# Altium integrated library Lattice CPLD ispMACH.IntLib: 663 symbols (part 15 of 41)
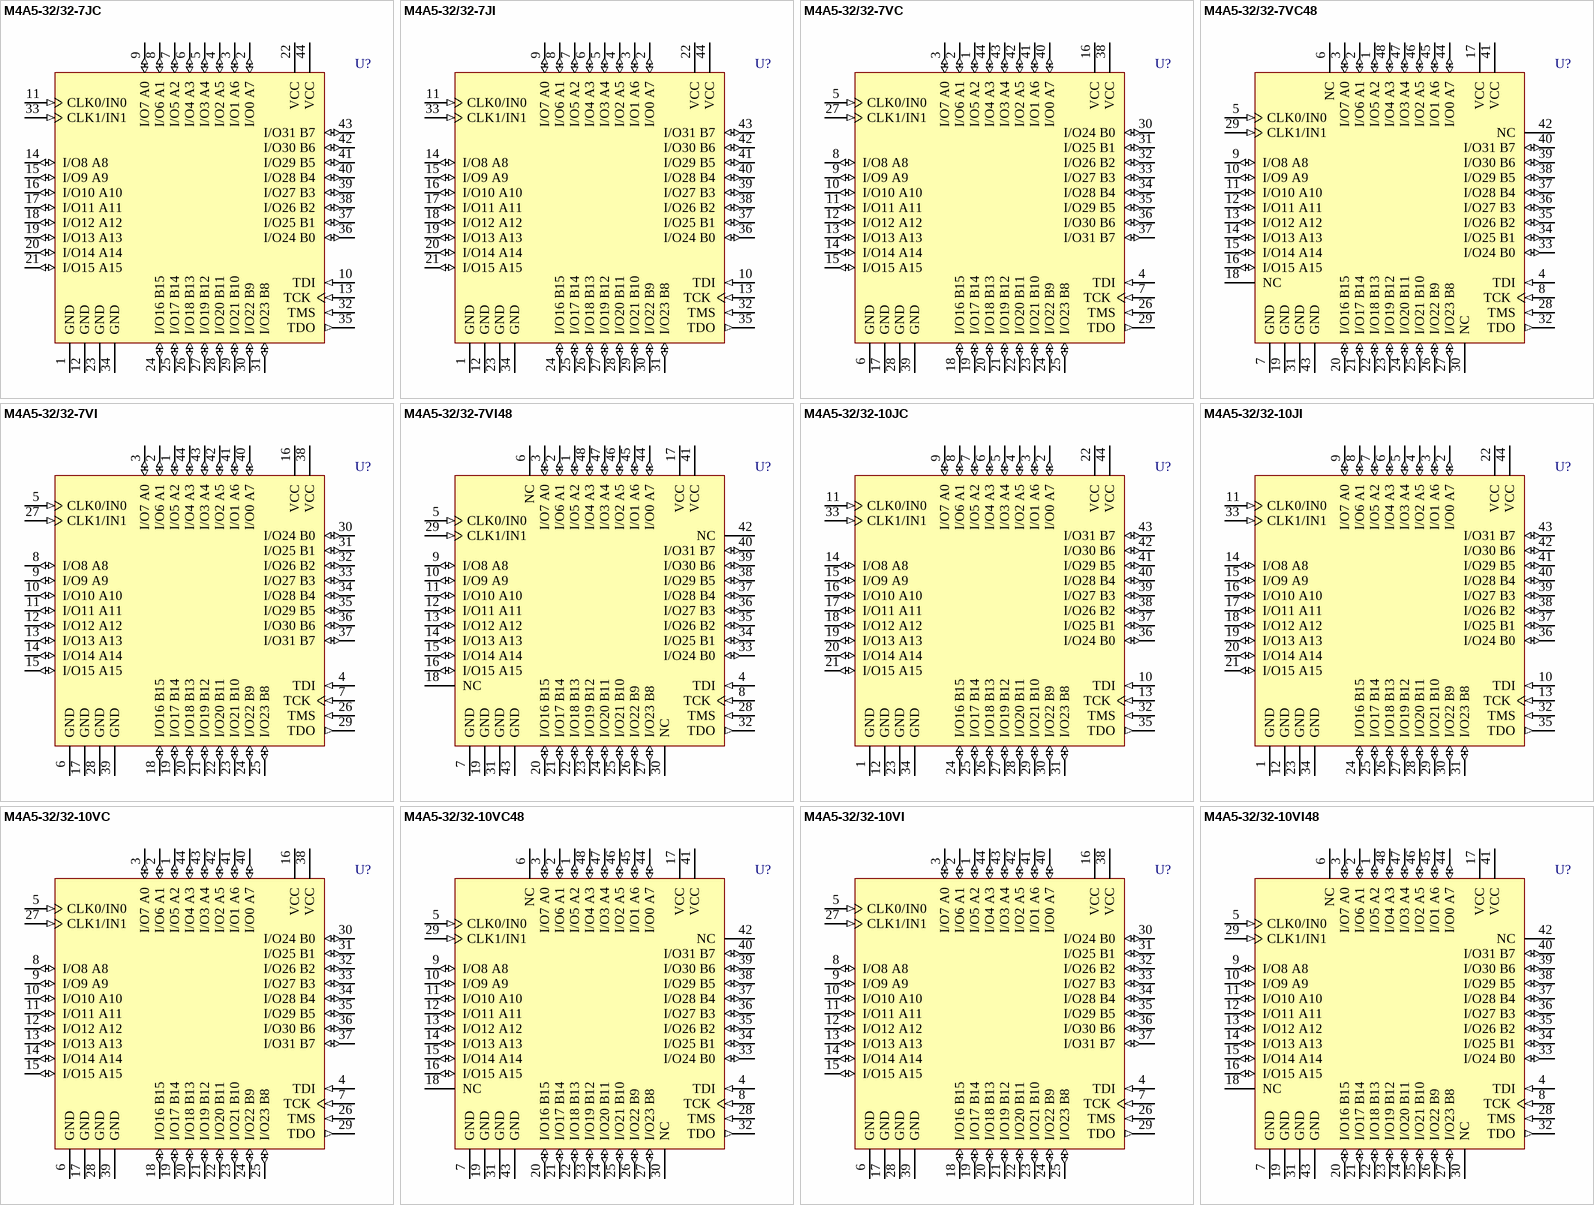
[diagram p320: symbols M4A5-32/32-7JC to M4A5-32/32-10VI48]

## M4A5-32/32-7JI
designator U?
High-Performance EE CMOS In-System Programmable Logic
footprint PLCC44_N (Leaded Chip Carrier, 44-Leads, Body 16.6x16.6mm, Pitch 1.27mm, IPC Medium Density)
footprint PLCC44_L (Leaded Chip Carrier, 44-Leads, Body 16.6x16.6mm, Pitch 1.27mm, IPC High Density)
footprint PLCC44_M (Leaded Chip Carrier, 44-Leads, Body 16.6x16.6mm, Pitch 1.27mm, IPC Low Density)
3D model M4A5-PLCC44 (44-Pin Leaded Chip Carrier 1.27 mm Pitch)
pins: 1 GND (power), 2 I/O0 A7 (io), 3 I/O1 A6 (io), 4 I/O2 A5 (io), 5 I/O3 A4 (io), 6 I/O4 A3 (io), 7 I/O5 A2 (io), 8 I/O6 A1 (io), 9 I/O7 A0 (io), 10 TDI (in), 11 CLK0/IN0 (in), 12 GND (power), 13 TCK (in), 14 I/O8 A8 (io), 15 I/O9 A9 (io), 16 I/O10 A10 (io), 17 I/O11 A11 (io), 18 I/O12 A12 (io), 19 I/O13 A13 (io), 20 I/O14 A14 (io), 21 I/O15 A15 (io), 22 VCC (power), 23 GND (power), 24 I/O16 B15 (io), 25 I/O17 B14 (io), 26 I/O18 B13 (io), 27 I/O19 B12 (io), 28 I/O20 B11 (io), 29 I/O21 B10 (io), 30 I/O22 B9 (io), 31 I/O23 B8 (io), 32 TMS (in), 33 CLK1/IN1 (in), 34 GND (power), 35 TDO (out), 36 I/O24 B0 (io), 37 I/O25 B1 (io), 38 I/O26 B2 (io), 39 I/O27 B3 (io), 40 I/O28 B4 (io), 41 I/O29 B5 (io), 42 I/O30 B6 (io), 43 I/O31 B7 (io), 44 VCC (power)

## M4A5-32/32-7VC
designator U?
High-Performance EE CMOS In-System Programmable Logic
footprint TQFP44_N (Thin QFP, 44-Leads, Body 10x10mm, Pitch 0.8mm, IPC Medium Density)
footprint TQFP44_L (Thin QFP, 44-Leads, Body 10x10mm, Pitch 0.8mm, IPC High Density)
footprint TQFP44_M (Thin QFP, 44-Leads, Body 10x10mm, Pitch 0.8mm, IPC Low Density)
3D model M4A5-TQFP44 (44-Pin Thin Quad Flat Pack 0.8 mm Pitch)
pins: 1 I/O5 A2 (io), 2 I/O6 A1 (io), 3 I/O7 A0 (io), 4 TDI (in), 5 CLK0/IN0 (in), 6 GND (power), 7 TCK (in), 8 I/O8 A8 (io), 9 I/O9 A9 (io), 10 I/O10 A10 (io), 11 I/O11 A11 (io), 12 I/O12 A12 (io), 13 I/O13 A13 (io), 14 I/O14 A14 (io), 15 I/O15 A15 (io), 16 VCC (power), 17 GND (power), 18 I/O16 B15 (io), 19 I/O17 B14 (io), 20 I/O18 B13 (io), 21 I/O19 B12 (io), 22 I/O20 B11 (io), 23 I/O21 B10 (io), 24 I/O22 B9 (io), 25 I/O23 B8 (io), 26 TMS (in), 27 CLK1/IN1 (in), 28 GND (power), 29 TDO (out), 30 I/O24 B0 (io), 31 I/O25 B1 (io), 32 I/O26 B2 (io), 33 I/O27 B3 (io), 34 I/O28 B4 (io), 35 I/O29 B5 (io), 36 I/O30 B6 (io), 37 I/O31 B7 (io), 38 VCC (power), 39 GND (power), 40 I/O0 A7 (io), 41 I/O1 A6 (io), 42 I/O2 A5 (io), 43 I/O3 A4 (io), 44 I/O4 A3 (io)

## M4A5-32/32-7VC48
designator U?
High-Performance EE CMOS In-System Programmable Logic
footprint TQFP48_N (Thin QFP, 48-Leads, Body 7x7mm, Pitch 0.5mm, IPC Medium Density)
footprint TQFP48_L (Thin QFP, 48-Leads, Body 7x7mm, Pitch 0.5mm, IPC High Density)
footprint TQFP48_M (Thin QFP, 48-Leads, Body 7x7mm, Pitch 0.5mm, IPC Low Density)
3D model M4A5-TQFP48 (48-Pin Thin Quad Flat Pack 0.5 mm Pitch)
pins: 1 I/O5 A2 (io), 2 I/O6 A1 (io), 3 I/O7 A0 (io), 4 TDI (in), 5 CLK0/IN0 (in), 6 NC, 7 GND (power), 8 TCK (in), 9 I/O8 A8 (io), 10 I/O9 A9 (io), 11 I/O10 A10 (io), 12 I/O11 A11 (io), 13 I/O12 A12 (io), 14 I/O13 A13 (io), 15 I/O14 A14 (io), 16 I/O15 A15 (io), 17 VCC (power), 18 NC, 19 GND (power), 20 I/O16 B15 (io), 21 I/O17 B14 (io), 22 I/O18 B13 (io), 23 I/O19 B12 (io), 24 I/O20 B11 (io), 25 I/O21 B10 (io), 26 I/O22 B9 (io), 27 I/O23 B8 (io), 28 TMS (in), 29 CLK1/IN1 (in), 30 NC, 31 GND (power), 32 TDO (out), 33 I/O24 B0 (io), 34 I/O25 B1 (io), 35 I/O26 B2 (io), 36 I/O27 B3 (io), 37 I/O28 B4 (io), 38 I/O29 B5 (io), 39 I/O30 B6 (io), 40 I/O31 B7 (io), 41 VCC (power), 42 NC, 43 GND (power), 44 I/O0 A7 (io), 45 I/O1 A6 (io), 46 I/O2 A5 (io), 47 I/O3 A4 (io), 48 I/O4 A3 (io)

## M4A5-32/32-7VI
designator U?
High-Performance EE CMOS In-System Programmable Logic
footprint TQFP44_N (Thin QFP, 44-Leads, Body 10x10mm, Pitch 0.8mm, IPC Medium Density)
footprint TQFP44_L (Thin QFP, 44-Leads, Body 10x10mm, Pitch 0.8mm, IPC High Density)
footprint TQFP44_M (Thin QFP, 44-Leads, Body 10x10mm, Pitch 0.8mm, IPC Low Density)
3D model M4A5-TQFP44 (44-Pin Thin Quad Flat Pack 0.8 mm Pitch)
pins: 1 I/O5 A2 (io), 2 I/O6 A1 (io), 3 I/O7 A0 (io), 4 TDI (in), 5 CLK0/IN0 (in), 6 GND (power), 7 TCK (in), 8 I/O8 A8 (io), 9 I/O9 A9 (io), 10 I/O10 A10 (io), 11 I/O11 A11 (io), 12 I/O12 A12 (io), 13 I/O13 A13 (io), 14 I/O14 A14 (io), 15 I/O15 A15 (io), 16 VCC (power), 17 GND (power), 18 I/O16 B15 (io), 19 I/O17 B14 (io), 20 I/O18 B13 (io), 21 I/O19 B12 (io), 22 I/O20 B11 (io), 23 I/O21 B10 (io), 24 I/O22 B9 (io), 25 I/O23 B8 (io), 26 TMS (in), 27 CLK1/IN1 (in), 28 GND (power), 29 TDO (out), 30 I/O24 B0 (io), 31 I/O25 B1 (io), 32 I/O26 B2 (io), 33 I/O27 B3 (io), 34 I/O28 B4 (io), 35 I/O29 B5 (io), 36 I/O30 B6 (io), 37 I/O31 B7 (io), 38 VCC (power), 39 GND (power), 40 I/O0 A7 (io), 41 I/O1 A6 (io), 42 I/O2 A5 (io), 43 I/O3 A4 (io), 44 I/O4 A3 (io)

## M4A5-32/32-7VI48
designator U?
High-Performance EE CMOS In-System Programmable Logic
footprint TQFP48_N (Thin QFP, 48-Leads, Body 7x7mm, Pitch 0.5mm, IPC Medium Density)
footprint TQFP48_L (Thin QFP, 48-Leads, Body 7x7mm, Pitch 0.5mm, IPC High Density)
footprint TQFP48_M (Thin QFP, 48-Leads, Body 7x7mm, Pitch 0.5mm, IPC Low Density)
3D model M4A5-TQFP48 (48-Pin Thin Quad Flat Pack 0.5 mm Pitch)
pins: 1 I/O5 A2 (io), 2 I/O6 A1 (io), 3 I/O7 A0 (io), 4 TDI (in), 5 CLK0/IN0 (in), 6 NC, 7 GND (power), 8 TCK (in), 9 I/O8 A8 (io), 10 I/O9 A9 (io), 11 I/O10 A10 (io), 12 I/O11 A11 (io), 13 I/O12 A12 (io), 14 I/O13 A13 (io), 15 I/O14 A14 (io), 16 I/O15 A15 (io), 17 VCC (power), 18 NC, 19 GND (power), 20 I/O16 B15 (io), 21 I/O17 B14 (io), 22 I/O18 B13 (io), 23 I/O19 B12 (io), 24 I/O20 B11 (io), 25 I/O21 B10 (io), 26 I/O22 B9 (io), 27 I/O23 B8 (io), 28 TMS (in), 29 CLK1/IN1 (in), 30 NC, 31 GND (power), 32 TDO (out), 33 I/O24 B0 (io), 34 I/O25 B1 (io), 35 I/O26 B2 (io), 36 I/O27 B3 (io), 37 I/O28 B4 (io), 38 I/O29 B5 (io), 39 I/O30 B6 (io), 40 I/O31 B7 (io), 41 VCC (power), 42 NC, 43 GND (power), 44 I/O0 A7 (io), 45 I/O1 A6 (io), 46 I/O2 A5 (io), 47 I/O3 A4 (io), 48 I/O4 A3 (io)

## M4A5-32/32-10JC
designator U?
High-Performance EE CMOS In-System Programmable Logic
footprint PLCC44_N (Leaded Chip Carrier, 44-Leads, Body 16.6x16.6mm, Pitch 1.27mm, IPC Medium Density)
footprint PLCC44_L (Leaded Chip Carrier, 44-Leads, Body 16.6x16.6mm, Pitch 1.27mm, IPC High Density)
footprint PLCC44_M (Leaded Chip Carrier, 44-Leads, Body 16.6x16.6mm, Pitch 1.27mm, IPC Low Density)
3D model M4A5-PLCC44 (44-Pin Leaded Chip Carrier 1.27 mm Pitch)
pins: 1 GND (power), 2 I/O0 A7 (io), 3 I/O1 A6 (io), 4 I/O2 A5 (io), 5 I/O3 A4 (io), 6 I/O4 A3 (io), 7 I/O5 A2 (io), 8 I/O6 A1 (io), 9 I/O7 A0 (io), 10 TDI (in), 11 CLK0/IN0 (in), 12 GND (power), 13 TCK (in), 14 I/O8 A8 (io), 15 I/O9 A9 (io), 16 I/O10 A10 (io), 17 I/O11 A11 (io), 18 I/O12 A12 (io), 19 I/O13 A13 (io), 20 I/O14 A14 (io), 21 I/O15 A15 (io), 22 VCC (power), 23 GND (power), 24 I/O16 B15 (io), 25 I/O17 B14 (io), 26 I/O18 B13 (io), 27 I/O19 B12 (io), 28 I/O20 B11 (io), 29 I/O21 B10 (io), 30 I/O22 B9 (io), 31 I/O23 B8 (io), 32 TMS (in), 33 CLK1/IN1 (in), 34 GND (power), 35 TDO (out), 36 I/O24 B0 (io), 37 I/O25 B1 (io), 38 I/O26 B2 (io), 39 I/O27 B3 (io), 40 I/O28 B4 (io), 41 I/O29 B5 (io), 42 I/O30 B6 (io), 43 I/O31 B7 (io), 44 VCC (power)

## M4A5-32/32-10JI
designator U?
High-Performance EE CMOS In-System Programmable Logic
footprint PLCC44_N (Leaded Chip Carrier, 44-Leads, Body 16.6x16.6mm, Pitch 1.27mm, IPC Medium Density)
footprint PLCC44_L (Leaded Chip Carrier, 44-Leads, Body 16.6x16.6mm, Pitch 1.27mm, IPC High Density)
footprint PLCC44_M (Leaded Chip Carrier, 44-Leads, Body 16.6x16.6mm, Pitch 1.27mm, IPC Low Density)
3D model M4A5-PLCC44 (44-Pin Leaded Chip Carrier 1.27 mm Pitch)
pins: 1 GND (power), 2 I/O0 A7 (io), 3 I/O1 A6 (io), 4 I/O2 A5 (io), 5 I/O3 A4 (io), 6 I/O4 A3 (io), 7 I/O5 A2 (io), 8 I/O6 A1 (io), 9 I/O7 A0 (io), 10 TDI (in), 11 CLK0/IN0 (in), 12 GND (power), 13 TCK (in), 14 I/O8 A8 (io), 15 I/O9 A9 (io), 16 I/O10 A10 (io), 17 I/O11 A11 (io), 18 I/O12 A12 (io), 19 I/O13 A13 (io), 20 I/O14 A14 (io), 21 I/O15 A15 (io), 22 VCC (power), 23 GND (power), 24 I/O16 B15 (io), 25 I/O17 B14 (io), 26 I/O18 B13 (io), 27 I/O19 B12 (io), 28 I/O20 B11 (io), 29 I/O21 B10 (io), 30 I/O22 B9 (io), 31 I/O23 B8 (io), 32 TMS (in), 33 CLK1/IN1 (in), 34 GND (power), 35 TDO (out), 36 I/O24 B0 (io), 37 I/O25 B1 (io), 38 I/O26 B2 (io), 39 I/O27 B3 (io), 40 I/O28 B4 (io), 41 I/O29 B5 (io), 42 I/O30 B6 (io), 43 I/O31 B7 (io), 44 VCC (power)

## M4A5-32/32-10VC
designator U?
High-Performance EE CMOS In-System Programmable Logic
footprint TQFP44_N (Thin QFP, 44-Leads, Body 10x10mm, Pitch 0.8mm, IPC Medium Density)
footprint TQFP44_L (Thin QFP, 44-Leads, Body 10x10mm, Pitch 0.8mm, IPC High Density)
footprint TQFP44_M (Thin QFP, 44-Leads, Body 10x10mm, Pitch 0.8mm, IPC Low Density)
3D model M4A5-TQFP44 (44-Pin Thin Quad Flat Pack 0.8 mm Pitch)
pins: 1 I/O5 A2 (io), 2 I/O6 A1 (io), 3 I/O7 A0 (io), 4 TDI (in), 5 CLK0/IN0 (in), 6 GND (power), 7 TCK (in), 8 I/O8 A8 (io), 9 I/O9 A9 (io), 10 I/O10 A10 (io), 11 I/O11 A11 (io), 12 I/O12 A12 (io), 13 I/O13 A13 (io), 14 I/O14 A14 (io), 15 I/O15 A15 (io), 16 VCC (power), 17 GND (power), 18 I/O16 B15 (io), 19 I/O17 B14 (io), 20 I/O18 B13 (io), 21 I/O19 B12 (io), 22 I/O20 B11 (io), 23 I/O21 B10 (io), 24 I/O22 B9 (io), 25 I/O23 B8 (io), 26 TMS (in), 27 CLK1/IN1 (in), 28 GND (power), 29 TDO (out), 30 I/O24 B0 (io), 31 I/O25 B1 (io), 32 I/O26 B2 (io), 33 I/O27 B3 (io), 34 I/O28 B4 (io), 35 I/O29 B5 (io), 36 I/O30 B6 (io), 37 I/O31 B7 (io), 38 VCC (power), 39 GND (power), 40 I/O0 A7 (io), 41 I/O1 A6 (io), 42 I/O2 A5 (io), 43 I/O3 A4 (io), 44 I/O4 A3 (io)

## M4A5-32/32-10VC48
designator U?
High-Performance EE CMOS In-System Programmable Logic
footprint TQFP48_N (Thin QFP, 48-Leads, Body 7x7mm, Pitch 0.5mm, IPC Medium Density)
footprint TQFP48_L (Thin QFP, 48-Leads, Body 7x7mm, Pitch 0.5mm, IPC High Density)
footprint TQFP48_M (Thin QFP, 48-Leads, Body 7x7mm, Pitch 0.5mm, IPC Low Density)
3D model M4A5-TQFP48 (48-Pin Thin Quad Flat Pack 0.5 mm Pitch)
pins: 1 I/O5 A2 (io), 2 I/O6 A1 (io), 3 I/O7 A0 (io), 4 TDI (in), 5 CLK0/IN0 (in), 6 NC, 7 GND (power), 8 TCK (in), 9 I/O8 A8 (io), 10 I/O9 A9 (io), 11 I/O10 A10 (io), 12 I/O11 A11 (io), 13 I/O12 A12 (io), 14 I/O13 A13 (io), 15 I/O14 A14 (io), 16 I/O15 A15 (io), 17 VCC (power), 18 NC, 19 GND (power), 20 I/O16 B15 (io), 21 I/O17 B14 (io), 22 I/O18 B13 (io), 23 I/O19 B12 (io), 24 I/O20 B11 (io), 25 I/O21 B10 (io), 26 I/O22 B9 (io), 27 I/O23 B8 (io), 28 TMS (in), 29 CLK1/IN1 (in), 30 NC, 31 GND (power), 32 TDO (out), 33 I/O24 B0 (io), 34 I/O25 B1 (io), 35 I/O26 B2 (io), 36 I/O27 B3 (io), 37 I/O28 B4 (io), 38 I/O29 B5 (io), 39 I/O30 B6 (io), 40 I/O31 B7 (io), 41 VCC (power), 42 NC, 43 GND (power), 44 I/O0 A7 (io), 45 I/O1 A6 (io), 46 I/O2 A5 (io), 47 I/O3 A4 (io), 48 I/O4 A3 (io)

## M4A5-32/32-10VI
designator U?
High-Performance EE CMOS In-System Programmable Logic
footprint TQFP44_N (Thin QFP, 44-Leads, Body 10x10mm, Pitch 0.8mm, IPC Medium Density)
footprint TQFP44_L (Thin QFP, 44-Leads, Body 10x10mm, Pitch 0.8mm, IPC High Density)
footprint TQFP44_M (Thin QFP, 44-Leads, Body 10x10mm, Pitch 0.8mm, IPC Low Density)
3D model M4A5-TQFP44 (44-Pin Thin Quad Flat Pack 0.8 mm Pitch)
pins: 1 I/O5 A2 (io), 2 I/O6 A1 (io), 3 I/O7 A0 (io), 4 TDI (in), 5 CLK0/IN0 (in), 6 GND (power), 7 TCK (in), 8 I/O8 A8 (io), 9 I/O9 A9 (io), 10 I/O10 A10 (io), 11 I/O11 A11 (io), 12 I/O12 A12 (io), 13 I/O13 A13 (io), 14 I/O14 A14 (io), 15 I/O15 A15 (io), 16 VCC (power), 17 GND (power), 18 I/O16 B15 (io), 19 I/O17 B14 (io), 20 I/O18 B13 (io), 21 I/O19 B12 (io), 22 I/O20 B11 (io), 23 I/O21 B10 (io), 24 I/O22 B9 (io), 25 I/O23 B8 (io), 26 TMS (in), 27 CLK1/IN1 (in), 28 GND (power), 29 TDO (out), 30 I/O24 B0 (io), 31 I/O25 B1 (io), 32 I/O26 B2 (io), 33 I/O27 B3 (io), 34 I/O28 B4 (io), 35 I/O29 B5 (io), 36 I/O30 B6 (io), 37 I/O31 B7 (io), 38 VCC (power), 39 GND (power), 40 I/O0 A7 (io), 41 I/O1 A6 (io), 42 I/O2 A5 (io), 43 I/O3 A4 (io), 44 I/O4 A3 (io)

## M4A5-32/32-10VI48
designator U?
High-Performance EE CMOS In-System Programmable Logic
footprint TQFP48_N (Thin QFP, 48-Leads, Body 7x7mm, Pitch 0.5mm, IPC Medium Density)
footprint TQFP48_L (Thin QFP, 48-Leads, Body 7x7mm, Pitch 0.5mm, IPC High Density)
footprint TQFP48_M (Thin QFP, 48-Leads, Body 7x7mm, Pitch 0.5mm, IPC Low Density)
3D model M4A5-TQFP48 (48-Pin Thin Quad Flat Pack 0.5 mm Pitch)
pins: 1 I/O5 A2 (io), 2 I/O6 A1 (io), 3 I/O7 A0 (io), 4 TDI (in), 5 CLK0/IN0 (in), 6 NC, 7 GND (power), 8 TCK (in), 9 I/O8 A8 (io), 10 I/O9 A9 (io), 11 I/O10 A10 (io), 12 I/O11 A11 (io), 13 I/O12 A12 (io), 14 I/O13 A13 (io), 15 I/O14 A14 (io), 16 I/O15 A15 (io), 17 VCC (power), 18 NC, 19 GND (power), 20 I/O16 B15 (io), 21 I/O17 B14 (io), 22 I/O18 B13 (io), 23 I/O19 B12 (io), 24 I/O20 B11 (io), 25 I/O21 B10 (io), 26 I/O22 B9 (io), 27 I/O23 B8 (io), 28 TMS (in), 29 CLK1/IN1 (in), 30 NC, 31 GND (power), 32 TDO (out), 33 I/O24 B0 (io), 34 I/O25 B1 (io), 35 I/O26 B2 (io), 36 I/O27 B3 (io), 37 I/O28 B4 (io), 38 I/O29 B5 (io), 39 I/O30 B6 (io), 40 I/O31 B7 (io), 41 VCC (power), 42 NC, 43 GND (power), 44 I/O0 A7 (io), 45 I/O1 A6 (io), 46 I/O2 A5 (io), 47 I/O3 A4 (io), 48 I/O4 A3 (io)

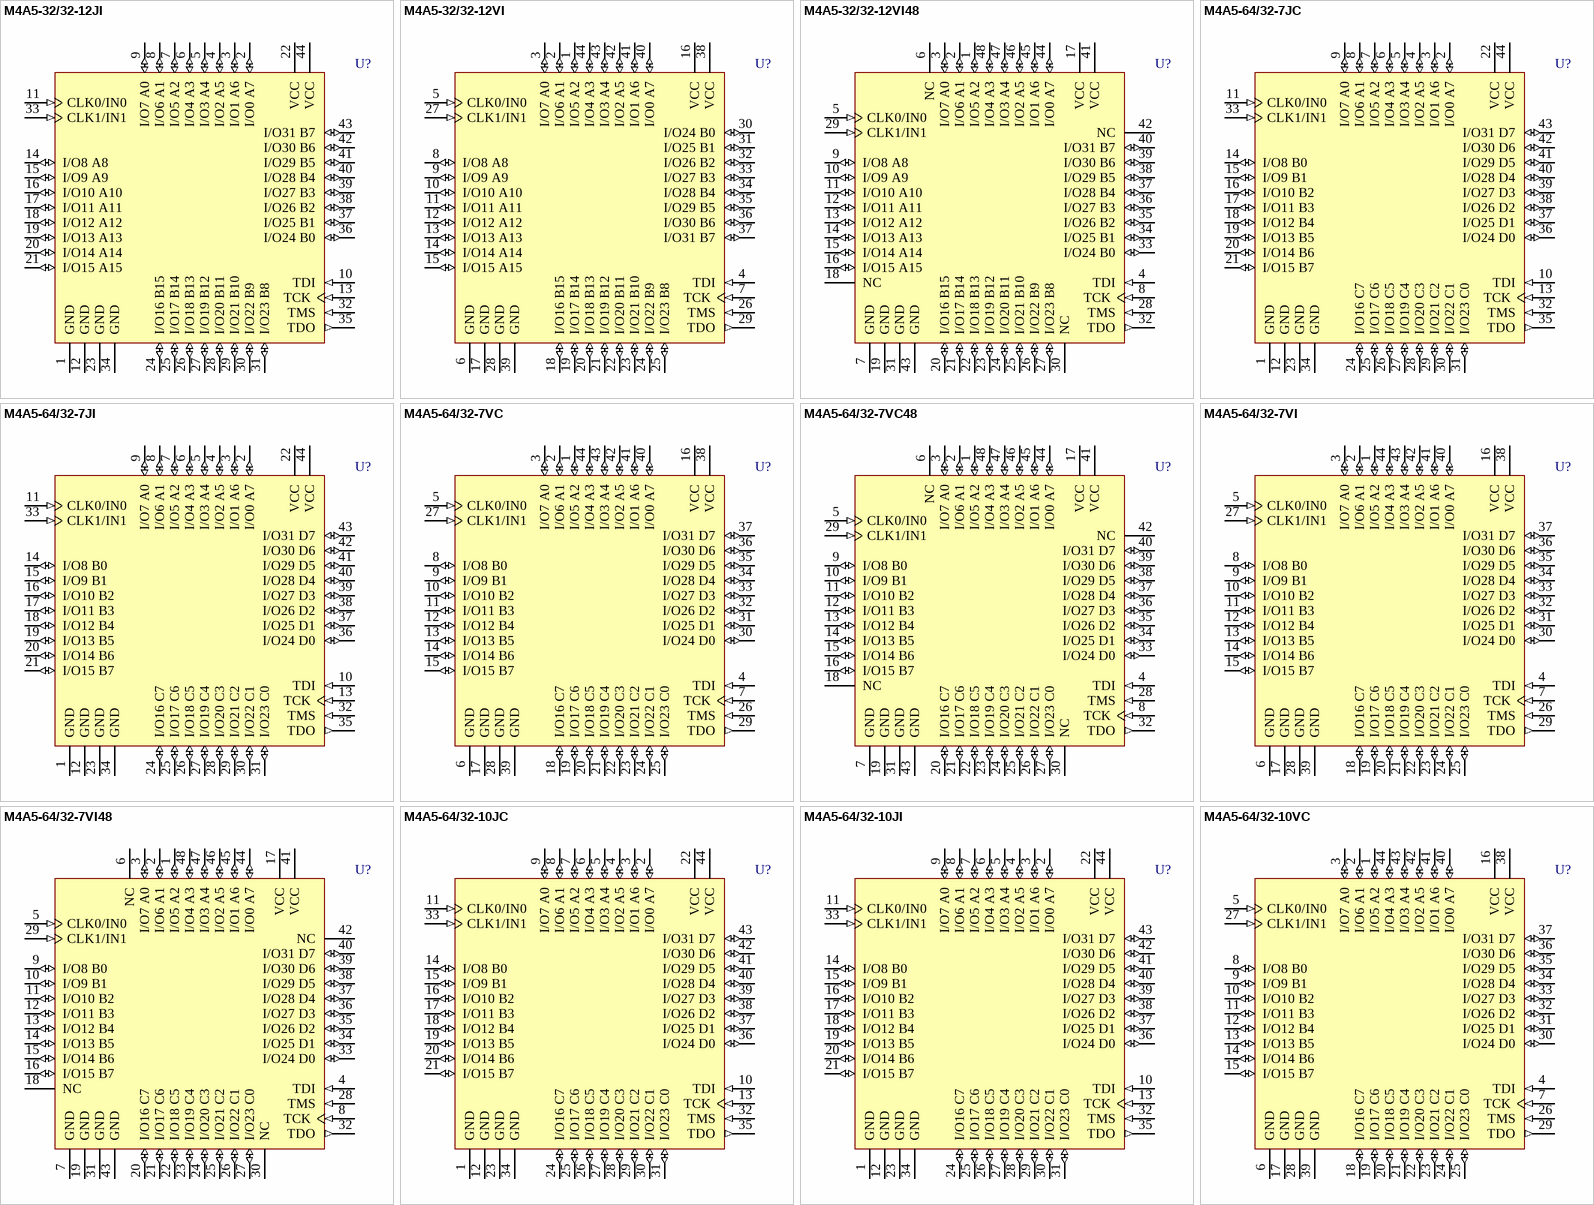
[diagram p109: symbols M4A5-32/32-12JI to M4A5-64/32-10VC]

## M4A5-32/32-12JI
designator U?
High-Performance EE CMOS In-System Programmable Logic
footprint PLCC44_N (Leaded Chip Carrier, 44-Leads, Body 16.6x16.6mm, Pitch 1.27mm, IPC Medium Density)
footprint PLCC44_L (Leaded Chip Carrier, 44-Leads, Body 16.6x16.6mm, Pitch 1.27mm, IPC High Density)
footprint PLCC44_M (Leaded Chip Carrier, 44-Leads, Body 16.6x16.6mm, Pitch 1.27mm, IPC Low Density)
3D model M4A5-PLCC44 (44-Pin Leaded Chip Carrier 1.27 mm Pitch)
pins: 1 GND (power), 2 I/O0 A7 (io), 3 I/O1 A6 (io), 4 I/O2 A5 (io), 5 I/O3 A4 (io), 6 I/O4 A3 (io), 7 I/O5 A2 (io), 8 I/O6 A1 (io), 9 I/O7 A0 (io), 10 TDI (in), 11 CLK0/IN0 (in), 12 GND (power), 13 TCK (in), 14 I/O8 A8 (io), 15 I/O9 A9 (io), 16 I/O10 A10 (io), 17 I/O11 A11 (io), 18 I/O12 A12 (io), 19 I/O13 A13 (io), 20 I/O14 A14 (io), 21 I/O15 A15 (io), 22 VCC (power), 23 GND (power), 24 I/O16 B15 (io), 25 I/O17 B14 (io), 26 I/O18 B13 (io), 27 I/O19 B12 (io), 28 I/O20 B11 (io), 29 I/O21 B10 (io), 30 I/O22 B9 (io), 31 I/O23 B8 (io), 32 TMS (in), 33 CLK1/IN1 (in), 34 GND (power), 35 TDO (out), 36 I/O24 B0 (io), 37 I/O25 B1 (io), 38 I/O26 B2 (io), 39 I/O27 B3 (io), 40 I/O28 B4 (io), 41 I/O29 B5 (io), 42 I/O30 B6 (io), 43 I/O31 B7 (io), 44 VCC (power)

## M4A5-32/32-12VI
designator U?
High-Performance EE CMOS In-System Programmable Logic
footprint TQFP44_N (Thin QFP, 44-Leads, Body 10x10mm, Pitch 0.8mm, IPC Medium Density)
footprint TQFP44_L (Thin QFP, 44-Leads, Body 10x10mm, Pitch 0.8mm, IPC High Density)
footprint TQFP44_M (Thin QFP, 44-Leads, Body 10x10mm, Pitch 0.8mm, IPC Low Density)
3D model M4A5-TQFP44 (44-Pin Thin Quad Flat Pack 0.8 mm Pitch)
pins: 1 I/O5 A2 (io), 2 I/O6 A1 (io), 3 I/O7 A0 (io), 4 TDI (in), 5 CLK0/IN0 (in), 6 GND (power), 7 TCK (in), 8 I/O8 A8 (io), 9 I/O9 A9 (io), 10 I/O10 A10 (io), 11 I/O11 A11 (io), 12 I/O12 A12 (io), 13 I/O13 A13 (io), 14 I/O14 A14 (io), 15 I/O15 A15 (io), 16 VCC (power), 17 GND (power), 18 I/O16 B15 (io), 19 I/O17 B14 (io), 20 I/O18 B13 (io), 21 I/O19 B12 (io), 22 I/O20 B11 (io), 23 I/O21 B10 (io), 24 I/O22 B9 (io), 25 I/O23 B8 (io), 26 TMS (in), 27 CLK1/IN1 (in), 28 GND (power), 29 TDO (out), 30 I/O24 B0 (io), 31 I/O25 B1 (io), 32 I/O26 B2 (io), 33 I/O27 B3 (io), 34 I/O28 B4 (io), 35 I/O29 B5 (io), 36 I/O30 B6 (io), 37 I/O31 B7 (io), 38 VCC (power), 39 GND (power), 40 I/O0 A7 (io), 41 I/O1 A6 (io), 42 I/O2 A5 (io), 43 I/O3 A4 (io), 44 I/O4 A3 (io)

## M4A5-32/32-12VI48
designator U?
High-Performance EE CMOS In-System Programmable Logic
footprint TQFP48_N (Thin QFP, 48-Leads, Body 7x7mm, Pitch 0.5mm, IPC Medium Density)
footprint TQFP48_L (Thin QFP, 48-Leads, Body 7x7mm, Pitch 0.5mm, IPC High Density)
footprint TQFP48_M (Thin QFP, 48-Leads, Body 7x7mm, Pitch 0.5mm, IPC Low Density)
3D model M4A5-TQFP48 (48-Pin Thin Quad Flat Pack 0.5 mm Pitch)
pins: 1 I/O5 A2 (io), 2 I/O6 A1 (io), 3 I/O7 A0 (io), 4 TDI (in), 5 CLK0/IN0 (in), 6 NC, 7 GND (power), 8 TCK (in), 9 I/O8 A8 (io), 10 I/O9 A9 (io), 11 I/O10 A10 (io), 12 I/O11 A11 (io), 13 I/O12 A12 (io), 14 I/O13 A13 (io), 15 I/O14 A14 (io), 16 I/O15 A15 (io), 17 VCC (power), 18 NC, 19 GND (power), 20 I/O16 B15 (io), 21 I/O17 B14 (io), 22 I/O18 B13 (io), 23 I/O19 B12 (io), 24 I/O20 B11 (io), 25 I/O21 B10 (io), 26 I/O22 B9 (io), 27 I/O23 B8 (io), 28 TMS (in), 29 CLK1/IN1 (in), 30 NC, 31 GND (power), 32 TDO (out), 33 I/O24 B0 (io), 34 I/O25 B1 (io), 35 I/O26 B2 (io), 36 I/O27 B3 (io), 37 I/O28 B4 (io), 38 I/O29 B5 (io), 39 I/O30 B6 (io), 40 I/O31 B7 (io), 41 VCC (power), 42 NC, 43 GND (power), 44 I/O0 A7 (io), 45 I/O1 A6 (io), 46 I/O2 A5 (io), 47 I/O3 A4 (io), 48 I/O4 A3 (io)

## M4A5-64/32-7JC
designator U?
High-Performance EE CMOS In-System Programmable Logic
footprint PLCC44_N (Leaded Chip Carrier, 44-Leads, Body 16.6x16.6mm, Pitch 1.27mm, IPC Medium Density)
footprint PLCC44_L (Leaded Chip Carrier, 44-Leads, Body 16.6x16.6mm, Pitch 1.27mm, IPC High Density)
footprint PLCC44_M (Leaded Chip Carrier, 44-Leads, Body 16.6x16.6mm, Pitch 1.27mm, IPC Low Density)
3D model M4A5-PLCC44 (44-Pin Leaded Chip Carrier 1.27 mm Pitch)
pins: 1 GND (power), 2 I/O0 A7 (io), 3 I/O1 A6 (io), 4 I/O2 A5 (io), 5 I/O3 A4 (io), 6 I/O4 A3 (io), 7 I/O5 A2 (io), 8 I/O6 A1 (io), 9 I/O7 A0 (io), 10 TDI (in), 11 CLK0/IN0 (in), 12 GND (power), 13 TCK (in), 14 I/O8 B0 (io), 15 I/O9 B1 (io), 16 I/O10 B2 (io), 17 I/O11 B3 (io), 18 I/O12 B4 (io), 19 I/O13 B5 (io), 20 I/O14 B6 (io), 21 I/O15 B7 (io), 22 VCC (power), 23 GND (power), 24 I/O16 C7 (io), 25 I/O17 C6 (io), 26 I/O18 C5 (io), 27 I/O19 C4 (io), 28 I/O20 C3 (io), 29 I/O21 C2 (io), 30 I/O22 C1 (io), 31 I/O23 C0 (io), 32 TMS (in), 33 CLK1/IN1 (in), 34 GND (power), 35 TDO (out), 36 I/O24 D0 (io), 37 I/O25 D1 (io), 38 I/O26 D2 (io), 39 I/O27 D3 (io), 40 I/O28 D4 (io), 41 I/O29 D5 (io), 42 I/O30 D6 (io), 43 I/O31 D7 (io), 44 VCC (power)

## M4A5-64/32-7JI
designator U?
High-Performance EE CMOS In-System Programmable Logic
footprint PLCC44_N (Leaded Chip Carrier, 44-Leads, Body 16.6x16.6mm, Pitch 1.27mm, IPC Medium Density)
footprint PLCC44_L (Leaded Chip Carrier, 44-Leads, Body 16.6x16.6mm, Pitch 1.27mm, IPC High Density)
footprint PLCC44_M (Leaded Chip Carrier, 44-Leads, Body 16.6x16.6mm, Pitch 1.27mm, IPC Low Density)
3D model M4A5-PLCC44 (44-Pin Leaded Chip Carrier 1.27 mm Pitch)
pins: 1 GND (power), 2 I/O0 A7 (io), 3 I/O1 A6 (io), 4 I/O2 A5 (io), 5 I/O3 A4 (io), 6 I/O4 A3 (io), 7 I/O5 A2 (io), 8 I/O6 A1 (io), 9 I/O7 A0 (io), 10 TDI (in), 11 CLK0/IN0 (in), 12 GND (power), 13 TCK (in), 14 I/O8 B0 (io), 15 I/O9 B1 (io), 16 I/O10 B2 (io), 17 I/O11 B3 (io), 18 I/O12 B4 (io), 19 I/O13 B5 (io), 20 I/O14 B6 (io), 21 I/O15 B7 (io), 22 VCC (power), 23 GND (power), 24 I/O16 C7 (io), 25 I/O17 C6 (io), 26 I/O18 C5 (io), 27 I/O19 C4 (io), 28 I/O20 C3 (io), 29 I/O21 C2 (io), 30 I/O22 C1 (io), 31 I/O23 C0 (io), 32 TMS (in), 33 CLK1/IN1 (in), 34 GND (power), 35 TDO (out), 36 I/O24 D0 (io), 37 I/O25 D1 (io), 38 I/O26 D2 (io), 39 I/O27 D3 (io), 40 I/O28 D4 (io), 41 I/O29 D5 (io), 42 I/O30 D6 (io), 43 I/O31 D7 (io), 44 VCC (power)

## M4A5-64/32-7VC
designator U?
High-Performance EE CMOS In-System Programmable Logic
footprint TQFP44_N (Thin QFP, 44-Leads, Body 10x10mm, Pitch 0.8mm, IPC Medium Density)
footprint TQFP44_L (Thin QFP, 44-Leads, Body 10x10mm, Pitch 0.8mm, IPC High Density)
footprint TQFP44_M (Thin QFP, 44-Leads, Body 10x10mm, Pitch 0.8mm, IPC Low Density)
3D model M4A5-TQFP44 (44-Pin Thin Quad Flat Pack 0.8 mm Pitch)
pins: 1 I/O5 A2 (io), 2 I/O6 A1 (io), 3 I/O7 A0 (io), 4 TDI (in), 5 CLK0/IN0 (in), 6 GND (power), 7 TCK (in), 8 I/O8 B0 (io), 9 I/O9 B1 (io), 10 I/O10 B2 (io), 11 I/O11 B3 (io), 12 I/O12 B4 (io), 13 I/O13 B5 (io), 14 I/O14 B6 (io), 15 I/O15 B7 (io), 16 VCC (power), 17 GND (power), 18 I/O16 C7 (io), 19 I/O17 C6 (io), 20 I/O18 C5 (io), 21 I/O19 C4 (io), 22 I/O20 C3 (io), 23 I/O21 C2 (io), 24 I/O22 C1 (io), 25 I/O23 C0 (io), 26 TMS (in), 27 CLK1/IN1 (in), 28 GND (power), 29 TDO (out), 30 I/O24 D0 (io), 31 I/O25 D1 (io), 32 I/O26 D2 (io), 33 I/O27 D3 (io), 34 I/O28 D4 (io), 35 I/O29 D5 (io), 36 I/O30 D6 (io), 37 I/O31 D7 (io), 38 VCC (power), 39 GND (power), 40 I/O0 A7 (io), 41 I/O1 A6 (io), 42 I/O2 A5 (io), 43 I/O3 A4 (io), 44 I/O4 A3 (io)

## M4A5-64/32-7VC48
designator U?
High-Performance EE CMOS In-System Programmable Logic
footprint TQFP48_N (Thin QFP, 48-Leads, Body 7x7mm, Pitch 0.5mm, IPC Medium Density)
footprint TQFP48_L (Thin QFP, 48-Leads, Body 7x7mm, Pitch 0.5mm, IPC High Density)
footprint TQFP48_M (Thin QFP, 48-Leads, Body 7x7mm, Pitch 0.5mm, IPC Low Density)
3D model M4A5-TQFP48 (48-Pin Thin Quad Flat Pack 0.5 mm Pitch)
pins: 1 I/O5 A2 (io), 2 I/O6 A1 (io), 3 I/O7 A0 (io), 4 TDI (in), 5 CLK0/IN0 (in), 6 NC, 7 GND (power), 8 TCK (in), 9 I/O8 B0 (io), 10 I/O9 B1 (io), 11 I/O10 B2 (io), 12 I/O11 B3 (io), 13 I/O12 B4 (io), 14 I/O13 B5 (io), 15 I/O14 B6 (io), 16 I/O15 B7 (io), 17 VCC (power), 18 NC, 19 GND (power), 20 I/O16 C7 (io), 21 I/O17 C6 (io), 22 I/O18 C5 (io), 23 I/O19 C4 (io), 24 I/O20 C3 (io), 25 I/O21 C2 (io), 26 I/O22 C1 (io), 27 I/O23 C0 (io), 28 TMS (in), 29 CLK1/IN1 (in), 30 NC, 31 GND (power), 32 TDO (out), 33 I/O24 D0 (io), 34 I/O25 D1 (io), 35 I/O26 D2 (io), 36 I/O27 D3 (io), 37 I/O28 D4 (io), 38 I/O29 D5 (io), 39 I/O30 D6 (io), 40 I/O31 D7 (io), 41 VCC (power), 42 NC, 43 GND (power), 44 I/O0 A7 (io), 45 I/O1 A6 (io), 46 I/O2 A5 (io), 47 I/O3 A4 (io), 48 I/O4 A3 (io)

## M4A5-64/32-7VI
designator U?
High-Performance EE CMOS In-System Programmable Logic
footprint TQFP44_N (Thin QFP, 44-Leads, Body 10x10mm, Pitch 0.8mm, IPC Medium Density)
footprint TQFP44_L (Thin QFP, 44-Leads, Body 10x10mm, Pitch 0.8mm, IPC High Density)
footprint TQFP44_M (Thin QFP, 44-Leads, Body 10x10mm, Pitch 0.8mm, IPC Low Density)
3D model M4A5-TQFP44 (44-Pin Thin Quad Flat Pack 0.8 mm Pitch)
pins: 1 I/O5 A2 (io), 2 I/O6 A1 (io), 3 I/O7 A0 (io), 4 TDI (in), 5 CLK0/IN0 (in), 6 GND (power), 7 TCK (in), 8 I/O8 B0 (io), 9 I/O9 B1 (io), 10 I/O10 B2 (io), 11 I/O11 B3 (io), 12 I/O12 B4 (io), 13 I/O13 B5 (io), 14 I/O14 B6 (io), 15 I/O15 B7 (io), 16 VCC (power), 17 GND (power), 18 I/O16 C7 (io), 19 I/O17 C6 (io), 20 I/O18 C5 (io), 21 I/O19 C4 (io), 22 I/O20 C3 (io), 23 I/O21 C2 (io), 24 I/O22 C1 (io), 25 I/O23 C0 (io), 26 TMS (in), 27 CLK1/IN1 (in), 28 GND (power), 29 TDO (out), 30 I/O24 D0 (io), 31 I/O25 D1 (io), 32 I/O26 D2 (io), 33 I/O27 D3 (io), 34 I/O28 D4 (io), 35 I/O29 D5 (io), 36 I/O30 D6 (io), 37 I/O31 D7 (io), 38 VCC (power), 39 GND (power), 40 I/O0 A7 (io), 41 I/O1 A6 (io), 42 I/O2 A5 (io), 43 I/O3 A4 (io), 44 I/O4 A3 (io)

## M4A5-64/32-7VI48
designator U?
High-Performance EE CMOS In-System Programmable Logic
footprint TQFP48_N (Thin QFP, 48-Leads, Body 7x7mm, Pitch 0.5mm, IPC Medium Density)
footprint TQFP48_L (Thin QFP, 48-Leads, Body 7x7mm, Pitch 0.5mm, IPC High Density)
footprint TQFP48_M (Thin QFP, 48-Leads, Body 7x7mm, Pitch 0.5mm, IPC Low Density)
3D model M4A5-TQFP48 (48-Pin Thin Quad Flat Pack 0.5 mm Pitch)
pins: 1 I/O5 A2 (io), 2 I/O6 A1 (io), 3 I/O7 A0 (io), 4 TDI (in), 5 CLK0/IN0 (in), 6 NC, 7 GND (power), 8 TCK (in), 9 I/O8 B0 (io), 10 I/O9 B1 (io), 11 I/O10 B2 (io), 12 I/O11 B3 (io), 13 I/O12 B4 (io), 14 I/O13 B5 (io), 15 I/O14 B6 (io), 16 I/O15 B7 (io), 17 VCC (power), 18 NC, 19 GND (power), 20 I/O16 C7 (io), 21 I/O17 C6 (io), 22 I/O18 C5 (io), 23 I/O19 C4 (io), 24 I/O20 C3 (io), 25 I/O21 C2 (io), 26 I/O22 C1 (io), 27 I/O23 C0 (io), 28 TMS (in), 29 CLK1/IN1 (in), 30 NC, 31 GND (power), 32 TDO (out), 33 I/O24 D0 (io), 34 I/O25 D1 (io), 35 I/O26 D2 (io), 36 I/O27 D3 (io), 37 I/O28 D4 (io), 38 I/O29 D5 (io), 39 I/O30 D6 (io), 40 I/O31 D7 (io), 41 VCC (power), 42 NC, 43 GND (power), 44 I/O0 A7 (io), 45 I/O1 A6 (io), 46 I/O2 A5 (io), 47 I/O3 A4 (io), 48 I/O4 A3 (io)

## M4A5-64/32-10JC
designator U?
High-Performance EE CMOS In-System Programmable Logic
footprint PLCC44_N (Leaded Chip Carrier, 44-Leads, Body 16.6x16.6mm, Pitch 1.27mm, IPC Medium Density)
footprint PLCC44_L (Leaded Chip Carrier, 44-Leads, Body 16.6x16.6mm, Pitch 1.27mm, IPC High Density)
footprint PLCC44_M (Leaded Chip Carrier, 44-Leads, Body 16.6x16.6mm, Pitch 1.27mm, IPC Low Density)
3D model M4A5-PLCC44 (44-Pin Leaded Chip Carrier 1.27 mm Pitch)
pins: 1 GND (power), 2 I/O0 A7 (io), 3 I/O1 A6 (io), 4 I/O2 A5 (io), 5 I/O3 A4 (io), 6 I/O4 A3 (io), 7 I/O5 A2 (io), 8 I/O6 A1 (io), 9 I/O7 A0 (io), 10 TDI (in), 11 CLK0/IN0 (in), 12 GND (power), 13 TCK (in), 14 I/O8 B0 (io), 15 I/O9 B1 (io), 16 I/O10 B2 (io), 17 I/O11 B3 (io), 18 I/O12 B4 (io), 19 I/O13 B5 (io), 20 I/O14 B6 (io), 21 I/O15 B7 (io), 22 VCC (power), 23 GND (power), 24 I/O16 C7 (io), 25 I/O17 C6 (io), 26 I/O18 C5 (io), 27 I/O19 C4 (io), 28 I/O20 C3 (io), 29 I/O21 C2 (io), 30 I/O22 C1 (io), 31 I/O23 C0 (io), 32 TMS (in), 33 CLK1/IN1 (in), 34 GND (power), 35 TDO (out), 36 I/O24 D0 (io), 37 I/O25 D1 (io), 38 I/O26 D2 (io), 39 I/O27 D3 (io), 40 I/O28 D4 (io), 41 I/O29 D5 (io), 42 I/O30 D6 (io), 43 I/O31 D7 (io), 44 VCC (power)

## M4A5-64/32-10JI
designator U?
High-Performance EE CMOS In-System Programmable Logic
footprint PLCC44_N (Leaded Chip Carrier, 44-Leads, Body 16.6x16.6mm, Pitch 1.27mm, IPC Medium Density)
footprint PLCC44_L (Leaded Chip Carrier, 44-Leads, Body 16.6x16.6mm, Pitch 1.27mm, IPC High Density)
footprint PLCC44_M (Leaded Chip Carrier, 44-Leads, Body 16.6x16.6mm, Pitch 1.27mm, IPC Low Density)
3D model M4A5-PLCC44 (44-Pin Leaded Chip Carrier 1.27 mm Pitch)
pins: 1 GND (power), 2 I/O0 A7 (io), 3 I/O1 A6 (io), 4 I/O2 A5 (io), 5 I/O3 A4 (io), 6 I/O4 A3 (io), 7 I/O5 A2 (io), 8 I/O6 A1 (io), 9 I/O7 A0 (io), 10 TDI (in), 11 CLK0/IN0 (in), 12 GND (power), 13 TCK (in), 14 I/O8 B0 (io), 15 I/O9 B1 (io), 16 I/O10 B2 (io), 17 I/O11 B3 (io), 18 I/O12 B4 (io), 19 I/O13 B5 (io), 20 I/O14 B6 (io), 21 I/O15 B7 (io), 22 VCC (power), 23 GND (power), 24 I/O16 C7 (io), 25 I/O17 C6 (io), 26 I/O18 C5 (io), 27 I/O19 C4 (io), 28 I/O20 C3 (io), 29 I/O21 C2 (io), 30 I/O22 C1 (io), 31 I/O23 C0 (io), 32 TMS (in), 33 CLK1/IN1 (in), 34 GND (power), 35 TDO (out), 36 I/O24 D0 (io), 37 I/O25 D1 (io), 38 I/O26 D2 (io), 39 I/O27 D3 (io), 40 I/O28 D4 (io), 41 I/O29 D5 (io), 42 I/O30 D6 (io), 43 I/O31 D7 (io), 44 VCC (power)

## M4A5-64/32-10VC
designator U?
High-Performance EE CMOS In-System Programmable Logic
footprint TQFP44_N (Thin QFP, 44-Leads, Body 10x10mm, Pitch 0.8mm, IPC Medium Density)
footprint TQFP44_L (Thin QFP, 44-Leads, Body 10x10mm, Pitch 0.8mm, IPC High Density)
footprint TQFP44_M (Thin QFP, 44-Leads, Body 10x10mm, Pitch 0.8mm, IPC Low Density)
3D model M4A5-TQFP44 (44-Pin Thin Quad Flat Pack 0.8 mm Pitch)
pins: 1 I/O5 A2 (io), 2 I/O6 A1 (io), 3 I/O7 A0 (io), 4 TDI (in), 5 CLK0/IN0 (in), 6 GND (power), 7 TCK (in), 8 I/O8 B0 (io), 9 I/O9 B1 (io), 10 I/O10 B2 (io), 11 I/O11 B3 (io), 12 I/O12 B4 (io), 13 I/O13 B5 (io), 14 I/O14 B6 (io), 15 I/O15 B7 (io), 16 VCC (power), 17 GND (power), 18 I/O16 C7 (io), 19 I/O17 C6 (io), 20 I/O18 C5 (io), 21 I/O19 C4 (io), 22 I/O20 C3 (io), 23 I/O21 C2 (io), 24 I/O22 C1 (io), 25 I/O23 C0 (io), 26 TMS (in), 27 CLK1/IN1 (in), 28 GND (power), 29 TDO (out), 30 I/O24 D0 (io), 31 I/O25 D1 (io), 32 I/O26 D2 (io), 33 I/O27 D3 (io), 34 I/O28 D4 (io), 35 I/O29 D5 (io), 36 I/O30 D6 (io), 37 I/O31 D7 (io), 38 VCC (power), 39 GND (power), 40 I/O0 A7 (io), 41 I/O1 A6 (io), 42 I/O2 A5 (io), 43 I/O3 A4 (io), 44 I/O4 A3 (io)

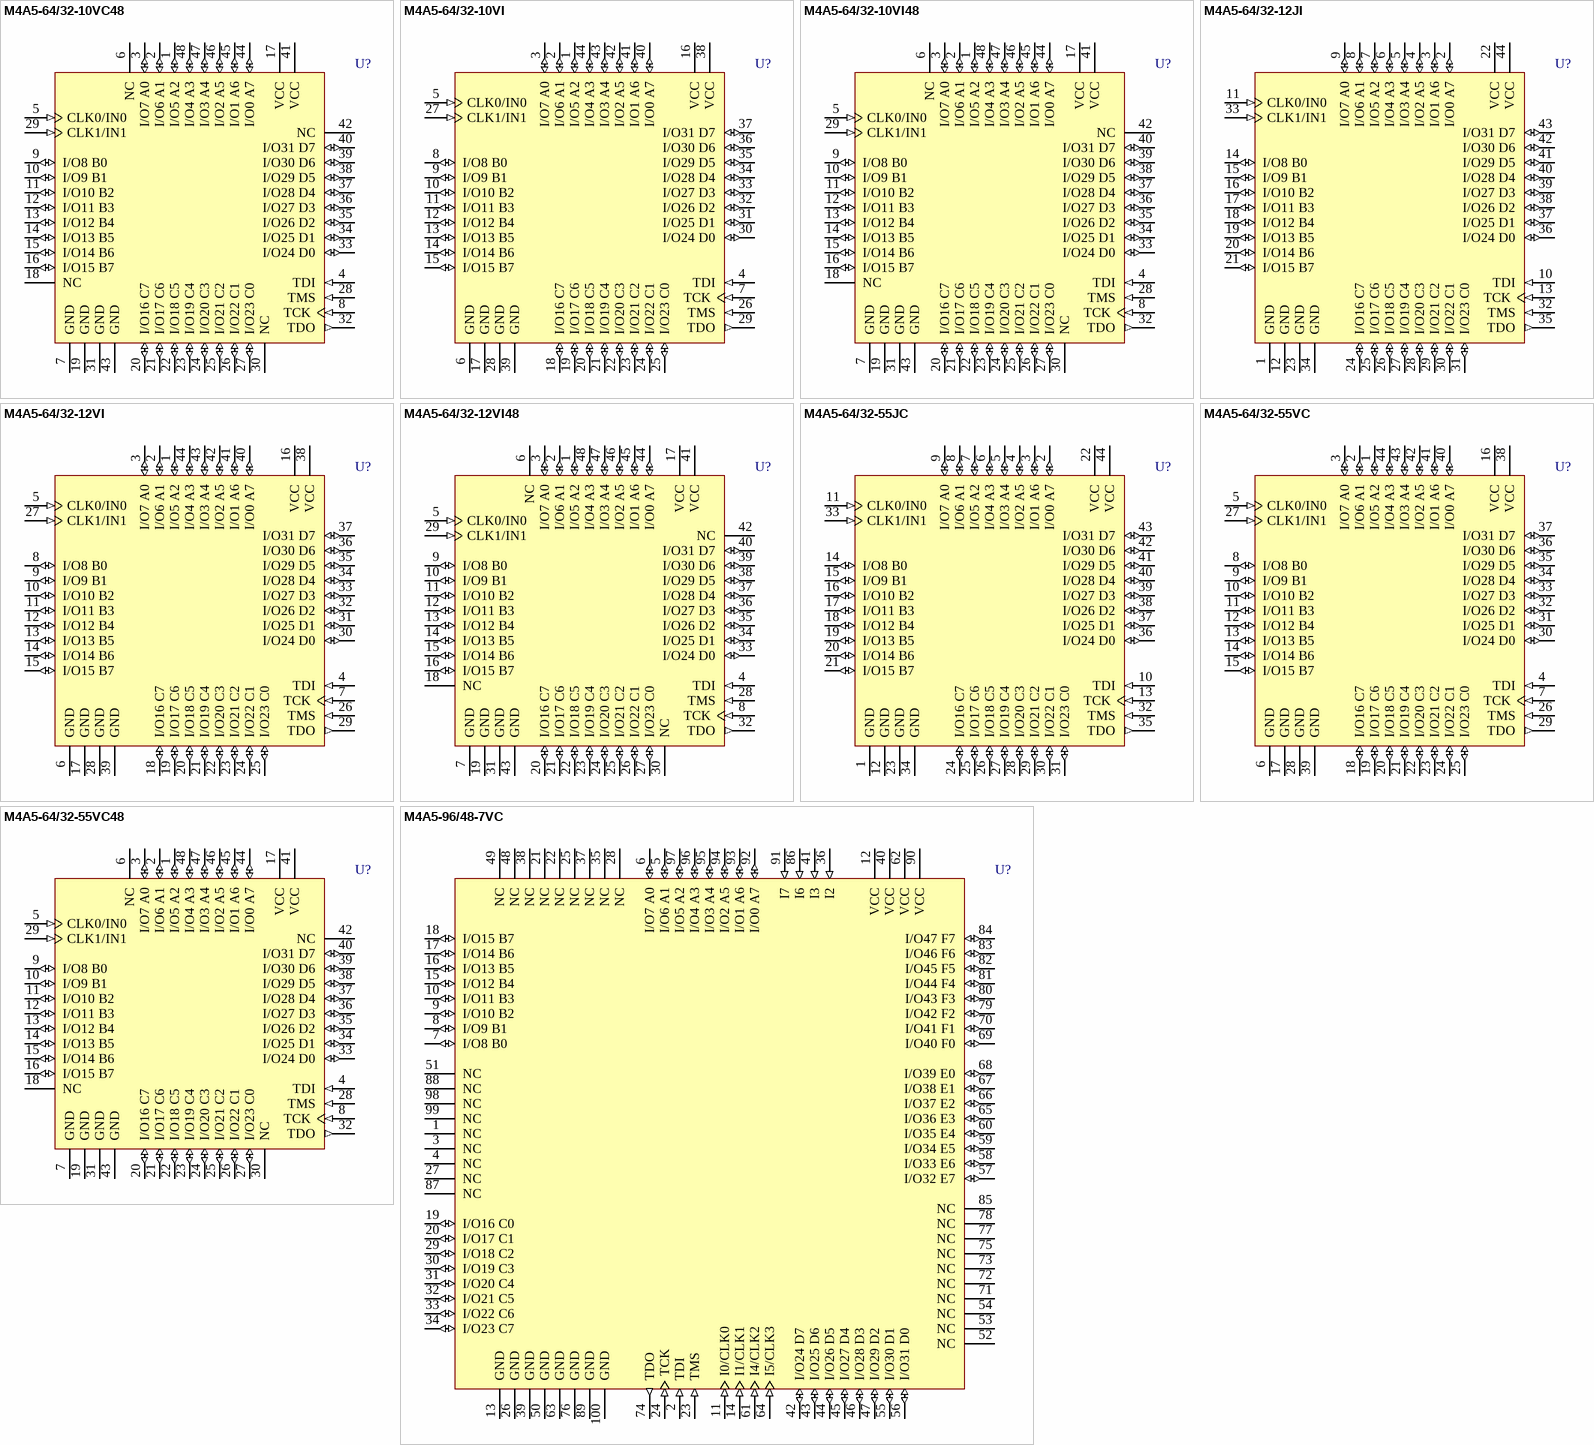
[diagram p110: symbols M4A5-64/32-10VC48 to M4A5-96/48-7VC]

## M4A5-64/32-10VC48
designator U?
High-Performance EE CMOS In-System Programmable Logic
footprint TQFP48_N (Thin QFP, 48-Leads, Body 7x7mm, Pitch 0.5mm, IPC Medium Density)
footprint TQFP48_L (Thin QFP, 48-Leads, Body 7x7mm, Pitch 0.5mm, IPC High Density)
footprint TQFP48_M (Thin QFP, 48-Leads, Body 7x7mm, Pitch 0.5mm, IPC Low Density)
3D model M4A5-TQFP48 (48-Pin Thin Quad Flat Pack 0.5 mm Pitch)
pins: 1 I/O5 A2 (io), 2 I/O6 A1 (io), 3 I/O7 A0 (io), 4 TDI (in), 5 CLK0/IN0 (in), 6 NC, 7 GND (power), 8 TCK (in), 9 I/O8 B0 (io), 10 I/O9 B1 (io), 11 I/O10 B2 (io), 12 I/O11 B3 (io), 13 I/O12 B4 (io), 14 I/O13 B5 (io), 15 I/O14 B6 (io), 16 I/O15 B7 (io), 17 VCC (power), 18 NC, 19 GND (power), 20 I/O16 C7 (io), 21 I/O17 C6 (io), 22 I/O18 C5 (io), 23 I/O19 C4 (io), 24 I/O20 C3 (io), 25 I/O21 C2 (io), 26 I/O22 C1 (io), 27 I/O23 C0 (io), 28 TMS (in), 29 CLK1/IN1 (in), 30 NC, 31 GND (power), 32 TDO (out), 33 I/O24 D0 (io), 34 I/O25 D1 (io), 35 I/O26 D2 (io), 36 I/O27 D3 (io), 37 I/O28 D4 (io), 38 I/O29 D5 (io), 39 I/O30 D6 (io), 40 I/O31 D7 (io), 41 VCC (power), 42 NC, 43 GND (power), 44 I/O0 A7 (io), 45 I/O1 A6 (io), 46 I/O2 A5 (io), 47 I/O3 A4 (io), 48 I/O4 A3 (io)

## M4A5-64/32-10VI
designator U?
High-Performance EE CMOS In-System Programmable Logic
footprint TQFP44_N (Thin QFP, 44-Leads, Body 10x10mm, Pitch 0.8mm, IPC Medium Density)
footprint TQFP44_L (Thin QFP, 44-Leads, Body 10x10mm, Pitch 0.8mm, IPC High Density)
footprint TQFP44_M (Thin QFP, 44-Leads, Body 10x10mm, Pitch 0.8mm, IPC Low Density)
3D model M4A5-TQFP44 (44-Pin Thin Quad Flat Pack 0.8 mm Pitch)
pins: 1 I/O5 A2 (io), 2 I/O6 A1 (io), 3 I/O7 A0 (io), 4 TDI (in), 5 CLK0/IN0 (in), 6 GND (power), 7 TCK (in), 8 I/O8 B0 (io), 9 I/O9 B1 (io), 10 I/O10 B2 (io), 11 I/O11 B3 (io), 12 I/O12 B4 (io), 13 I/O13 B5 (io), 14 I/O14 B6 (io), 15 I/O15 B7 (io), 16 VCC (power), 17 GND (power), 18 I/O16 C7 (io), 19 I/O17 C6 (io), 20 I/O18 C5 (io), 21 I/O19 C4 (io), 22 I/O20 C3 (io), 23 I/O21 C2 (io), 24 I/O22 C1 (io), 25 I/O23 C0 (io), 26 TMS (in), 27 CLK1/IN1 (in), 28 GND (power), 29 TDO (out), 30 I/O24 D0 (io), 31 I/O25 D1 (io), 32 I/O26 D2 (io), 33 I/O27 D3 (io), 34 I/O28 D4 (io), 35 I/O29 D5 (io), 36 I/O30 D6 (io), 37 I/O31 D7 (io), 38 VCC (power), 39 GND (power), 40 I/O0 A7 (io), 41 I/O1 A6 (io), 42 I/O2 A5 (io), 43 I/O3 A4 (io), 44 I/O4 A3 (io)

## M4A5-64/32-10VI48
designator U?
High-Performance EE CMOS In-System Programmable Logic
footprint TQFP48_N (Thin QFP, 48-Leads, Body 7x7mm, Pitch 0.5mm, IPC Medium Density)
footprint TQFP48_L (Thin QFP, 48-Leads, Body 7x7mm, Pitch 0.5mm, IPC High Density)
footprint TQFP48_M (Thin QFP, 48-Leads, Body 7x7mm, Pitch 0.5mm, IPC Low Density)
3D model M4A5-TQFP48 (48-Pin Thin Quad Flat Pack 0.5 mm Pitch)
pins: 1 I/O5 A2 (io), 2 I/O6 A1 (io), 3 I/O7 A0 (io), 4 TDI (in), 5 CLK0/IN0 (in), 6 NC, 7 GND (power), 8 TCK (in), 9 I/O8 B0 (io), 10 I/O9 B1 (io), 11 I/O10 B2 (io), 12 I/O11 B3 (io), 13 I/O12 B4 (io), 14 I/O13 B5 (io), 15 I/O14 B6 (io), 16 I/O15 B7 (io), 17 VCC (power), 18 NC, 19 GND (power), 20 I/O16 C7 (io), 21 I/O17 C6 (io), 22 I/O18 C5 (io), 23 I/O19 C4 (io), 24 I/O20 C3 (io), 25 I/O21 C2 (io), 26 I/O22 C1 (io), 27 I/O23 C0 (io), 28 TMS (in), 29 CLK1/IN1 (in), 30 NC, 31 GND (power), 32 TDO (out), 33 I/O24 D0 (io), 34 I/O25 D1 (io), 35 I/O26 D2 (io), 36 I/O27 D3 (io), 37 I/O28 D4 (io), 38 I/O29 D5 (io), 39 I/O30 D6 (io), 40 I/O31 D7 (io), 41 VCC (power), 42 NC, 43 GND (power), 44 I/O0 A7 (io), 45 I/O1 A6 (io), 46 I/O2 A5 (io), 47 I/O3 A4 (io), 48 I/O4 A3 (io)

## M4A5-64/32-12JI
designator U?
High-Performance EE CMOS In-System Programmable Logic
footprint PLCC44_N (Leaded Chip Carrier, 44-Leads, Body 16.6x16.6mm, Pitch 1.27mm, IPC Medium Density)
footprint PLCC44_L (Leaded Chip Carrier, 44-Leads, Body 16.6x16.6mm, Pitch 1.27mm, IPC High Density)
footprint PLCC44_M (Leaded Chip Carrier, 44-Leads, Body 16.6x16.6mm, Pitch 1.27mm, IPC Low Density)
3D model M4A5-PLCC44 (44-Pin Leaded Chip Carrier 1.27 mm Pitch)
pins: 1 GND (power), 2 I/O0 A7 (io), 3 I/O1 A6 (io), 4 I/O2 A5 (io), 5 I/O3 A4 (io), 6 I/O4 A3 (io), 7 I/O5 A2 (io), 8 I/O6 A1 (io), 9 I/O7 A0 (io), 10 TDI (in), 11 CLK0/IN0 (in), 12 GND (power), 13 TCK (in), 14 I/O8 B0 (io), 15 I/O9 B1 (io), 16 I/O10 B2 (io), 17 I/O11 B3 (io), 18 I/O12 B4 (io), 19 I/O13 B5 (io), 20 I/O14 B6 (io), 21 I/O15 B7 (io), 22 VCC (power), 23 GND (power), 24 I/O16 C7 (io), 25 I/O17 C6 (io), 26 I/O18 C5 (io), 27 I/O19 C4 (io), 28 I/O20 C3 (io), 29 I/O21 C2 (io), 30 I/O22 C1 (io), 31 I/O23 C0 (io), 32 TMS (in), 33 CLK1/IN1 (in), 34 GND (power), 35 TDO (out), 36 I/O24 D0 (io), 37 I/O25 D1 (io), 38 I/O26 D2 (io), 39 I/O27 D3 (io), 40 I/O28 D4 (io), 41 I/O29 D5 (io), 42 I/O30 D6 (io), 43 I/O31 D7 (io), 44 VCC (power)

## M4A5-64/32-12VI
designator U?
High-Performance EE CMOS In-System Programmable Logic
footprint TQFP44_N (Thin QFP, 44-Leads, Body 10x10mm, Pitch 0.8mm, IPC Medium Density)
footprint TQFP44_L (Thin QFP, 44-Leads, Body 10x10mm, Pitch 0.8mm, IPC High Density)
footprint TQFP44_M (Thin QFP, 44-Leads, Body 10x10mm, Pitch 0.8mm, IPC Low Density)
3D model M4A5-TQFP44 (44-Pin Thin Quad Flat Pack 0.8 mm Pitch)
pins: 1 I/O5 A2 (io), 2 I/O6 A1 (io), 3 I/O7 A0 (io), 4 TDI (in), 5 CLK0/IN0 (in), 6 GND (power), 7 TCK (in), 8 I/O8 B0 (io), 9 I/O9 B1 (io), 10 I/O10 B2 (io), 11 I/O11 B3 (io), 12 I/O12 B4 (io), 13 I/O13 B5 (io), 14 I/O14 B6 (io), 15 I/O15 B7 (io), 16 VCC (power), 17 GND (power), 18 I/O16 C7 (io), 19 I/O17 C6 (io), 20 I/O18 C5 (io), 21 I/O19 C4 (io), 22 I/O20 C3 (io), 23 I/O21 C2 (io), 24 I/O22 C1 (io), 25 I/O23 C0 (io), 26 TMS (in), 27 CLK1/IN1 (in), 28 GND (power), 29 TDO (out), 30 I/O24 D0 (io), 31 I/O25 D1 (io), 32 I/O26 D2 (io), 33 I/O27 D3 (io), 34 I/O28 D4 (io), 35 I/O29 D5 (io), 36 I/O30 D6 (io), 37 I/O31 D7 (io), 38 VCC (power), 39 GND (power), 40 I/O0 A7 (io), 41 I/O1 A6 (io), 42 I/O2 A5 (io), 43 I/O3 A4 (io), 44 I/O4 A3 (io)

## M4A5-64/32-12VI48
designator U?
High-Performance EE CMOS In-System Programmable Logic
footprint TQFP48_N (Thin QFP, 48-Leads, Body 7x7mm, Pitch 0.5mm, IPC Medium Density)
footprint TQFP48_L (Thin QFP, 48-Leads, Body 7x7mm, Pitch 0.5mm, IPC High Density)
footprint TQFP48_M (Thin QFP, 48-Leads, Body 7x7mm, Pitch 0.5mm, IPC Low Density)
3D model M4A5-TQFP48 (48-Pin Thin Quad Flat Pack 0.5 mm Pitch)
pins: 1 I/O5 A2 (io), 2 I/O6 A1 (io), 3 I/O7 A0 (io), 4 TDI (in), 5 CLK0/IN0 (in), 6 NC, 7 GND (power), 8 TCK (in), 9 I/O8 B0 (io), 10 I/O9 B1 (io), 11 I/O10 B2 (io), 12 I/O11 B3 (io), 13 I/O12 B4 (io), 14 I/O13 B5 (io), 15 I/O14 B6 (io), 16 I/O15 B7 (io), 17 VCC (power), 18 NC, 19 GND (power), 20 I/O16 C7 (io), 21 I/O17 C6 (io), 22 I/O18 C5 (io), 23 I/O19 C4 (io), 24 I/O20 C3 (io), 25 I/O21 C2 (io), 26 I/O22 C1 (io), 27 I/O23 C0 (io), 28 TMS (in), 29 CLK1/IN1 (in), 30 NC, 31 GND (power), 32 TDO (out), 33 I/O24 D0 (io), 34 I/O25 D1 (io), 35 I/O26 D2 (io), 36 I/O27 D3 (io), 37 I/O28 D4 (io), 38 I/O29 D5 (io), 39 I/O30 D6 (io), 40 I/O31 D7 (io), 41 VCC (power), 42 NC, 43 GND (power), 44 I/O0 A7 (io), 45 I/O1 A6 (io), 46 I/O2 A5 (io), 47 I/O3 A4 (io), 48 I/O4 A3 (io)

## M4A5-64/32-55JC
designator U?
High-Performance EE CMOS In-System Programmable Logic
footprint PLCC44_N (Leaded Chip Carrier, 44-Leads, Body 16.6x16.6mm, Pitch 1.27mm, IPC Medium Density)
footprint PLCC44_L (Leaded Chip Carrier, 44-Leads, Body 16.6x16.6mm, Pitch 1.27mm, IPC High Density)
footprint PLCC44_M (Leaded Chip Carrier, 44-Leads, Body 16.6x16.6mm, Pitch 1.27mm, IPC Low Density)
3D model M4A5-PLCC44 (44-Pin Leaded Chip Carrier 1.27 mm Pitch)
pins: 1 GND (power), 2 I/O0 A7 (io), 3 I/O1 A6 (io), 4 I/O2 A5 (io), 5 I/O3 A4 (io), 6 I/O4 A3 (io), 7 I/O5 A2 (io), 8 I/O6 A1 (io), 9 I/O7 A0 (io), 10 TDI (in), 11 CLK0/IN0 (in), 12 GND (power), 13 TCK (in), 14 I/O8 B0 (io), 15 I/O9 B1 (io), 16 I/O10 B2 (io), 17 I/O11 B3 (io), 18 I/O12 B4 (io), 19 I/O13 B5 (io), 20 I/O14 B6 (io), 21 I/O15 B7 (io), 22 VCC (power), 23 GND (power), 24 I/O16 C7 (io), 25 I/O17 C6 (io), 26 I/O18 C5 (io), 27 I/O19 C4 (io), 28 I/O20 C3 (io), 29 I/O21 C2 (io), 30 I/O22 C1 (io), 31 I/O23 C0 (io), 32 TMS (in), 33 CLK1/IN1 (in), 34 GND (power), 35 TDO (out), 36 I/O24 D0 (io), 37 I/O25 D1 (io), 38 I/O26 D2 (io), 39 I/O27 D3 (io), 40 I/O28 D4 (io), 41 I/O29 D5 (io), 42 I/O30 D6 (io), 43 I/O31 D7 (io), 44 VCC (power)

## M4A5-64/32-55VC
designator U?
High-Performance EE CMOS In-System Programmable Logic
footprint TQFP44_N (Thin QFP, 44-Leads, Body 10x10mm, Pitch 0.8mm, IPC Medium Density)
footprint TQFP44_L (Thin QFP, 44-Leads, Body 10x10mm, Pitch 0.8mm, IPC High Density)
footprint TQFP44_M (Thin QFP, 44-Leads, Body 10x10mm, Pitch 0.8mm, IPC Low Density)
3D model M4A5-TQFP44 (44-Pin Thin Quad Flat Pack 0.8 mm Pitch)
pins: 1 I/O5 A2 (io), 2 I/O6 A1 (io), 3 I/O7 A0 (io), 4 TDI (in), 5 CLK0/IN0 (in), 6 GND (power), 7 TCK (in), 8 I/O8 B0 (io), 9 I/O9 B1 (io), 10 I/O10 B2 (io), 11 I/O11 B3 (io), 12 I/O12 B4 (io), 13 I/O13 B5 (io), 14 I/O14 B6 (io), 15 I/O15 B7 (io), 16 VCC (power), 17 GND (power), 18 I/O16 C7 (io), 19 I/O17 C6 (io), 20 I/O18 C5 (io), 21 I/O19 C4 (io), 22 I/O20 C3 (io), 23 I/O21 C2 (io), 24 I/O22 C1 (io), 25 I/O23 C0 (io), 26 TMS (in), 27 CLK1/IN1 (in), 28 GND (power), 29 TDO (out), 30 I/O24 D0 (io), 31 I/O25 D1 (io), 32 I/O26 D2 (io), 33 I/O27 D3 (io), 34 I/O28 D4 (io), 35 I/O29 D5 (io), 36 I/O30 D6 (io), 37 I/O31 D7 (io), 38 VCC (power), 39 GND (power), 40 I/O0 A7 (io), 41 I/O1 A6 (io), 42 I/O2 A5 (io), 43 I/O3 A4 (io), 44 I/O4 A3 (io)

## M4A5-64/32-55VC48
designator U?
High-Performance EE CMOS In-System Programmable Logic
footprint TQFP48_N (Thin QFP, 48-Leads, Body 7x7mm, Pitch 0.5mm, IPC Medium Density)
footprint TQFP48_L (Thin QFP, 48-Leads, Body 7x7mm, Pitch 0.5mm, IPC High Density)
footprint TQFP48_M (Thin QFP, 48-Leads, Body 7x7mm, Pitch 0.5mm, IPC Low Density)
3D model M4A5-TQFP48 (48-Pin Thin Quad Flat Pack 0.5 mm Pitch)
pins: 1 I/O5 A2 (io), 2 I/O6 A1 (io), 3 I/O7 A0 (io), 4 TDI (in), 5 CLK0/IN0 (in), 6 NC, 7 GND (power), 8 TCK (in), 9 I/O8 B0 (io), 10 I/O9 B1 (io), 11 I/O10 B2 (io), 12 I/O11 B3 (io), 13 I/O12 B4 (io), 14 I/O13 B5 (io), 15 I/O14 B6 (io), 16 I/O15 B7 (io), 17 VCC (power), 18 NC, 19 GND (power), 20 I/O16 C7 (io), 21 I/O17 C6 (io), 22 I/O18 C5 (io), 23 I/O19 C4 (io), 24 I/O20 C3 (io), 25 I/O21 C2 (io), 26 I/O22 C1 (io), 27 I/O23 C0 (io), 28 TMS (in), 29 CLK1/IN1 (in), 30 NC, 31 GND (power), 32 TDO (out), 33 I/O24 D0 (io), 34 I/O25 D1 (io), 35 I/O26 D2 (io), 36 I/O27 D3 (io), 37 I/O28 D4 (io), 38 I/O29 D5 (io), 39 I/O30 D6 (io), 40 I/O31 D7 (io), 41 VCC (power), 42 NC, 43 GND (power), 44 I/O0 A7 (io), 45 I/O1 A6 (io), 46 I/O2 A5 (io), 47 I/O3 A4 (io), 48 I/O4 A3 (io)

## M4A5-96/48-7VC
designator U?
High-Performance EE CMOS In-System Programmable Logic
footprint TQFP100_N (Thin QFP, 100-Leads, Body 14x14mm, Pitch 0.5mm, IPC Medium Density)
footprint TQFP100_L (Thin QFP, 100-Leads, Body 14x14mm, Pitch 0.5mm, IPC High Density)
footprint TQFP100_M (Thin QFP, 100-Leads, Body 14x14mm, Pitch 0.5mm, IPC Low Density)
3D model M4A5-TQFP100 (100-Pin Thin Quad Flat Pack (TQFP100))
pins: 1 NC, 2 TDI (in), 3 NC, 4 NC, 5 I/O6 A1 (io), 6 I/O7 A0 (io), 7 I/O8 B0 (io), 8 I/O9 B1 (io), 9 I/O10 B2 (io), 10 I/O11 B3 (io), 11 I0/CLK0 (in), 12 VCC (power), 13 GND (power), 14 I1/CLK1 (in), 15 I/O12 B4 (io), 16 I/O13 B5 (io), 17 I/O14 B6 (io), 18 I/O15 B7 (io), 19 I/O16 C0 (io), 20 I/O17 C1 (io), 21 NC, 22 NC, 23 TMS (in), 24 TCK (in), 25 NC, 26 GND (power), 27 NC, 28 NC, 29 I/O18 C2 (io), 30 I/O19 C3 (io), 31 I/O20 C4 (io), 32 I/O21 C5 (io), 33 I/O22 C6 (io), 34 I/O23 C7 (io), 35 NC, 36 I2 (in), 37 NC, 38 NC, 39 GND (power), 40 VCC (power), 41 I3 (in), 42 I/O24 D7 (io), 43 I/O25 D6 (io), 44 I/O26 D5 (io), 45 I/O27 D4 (io), 46 I/O28 D3 (io), 47 I/O29 D2 (io), 48 NC, 49 NC, 50 GND (power), 51 NC, 52 NC, 53 NC, 54 NC, 55 I/O30 D1 (io), 56 I/O31 D0 (io), 57 I/O32 E7 (io), 58 I/O33 E6 (io), 59 I/O34 E5 (io), 60 I/O35 E4 (io), 61 I4/CLK2 (in), 62 VCC (power), 63 GND (power), 64 I5/CLK3 (in), 65 I/O36 E3 (io), 66 I/O37 E2 (io), 67 I/O38 E1 (io), 68 I/O39 E0 (io), 69 I/O40 F0 (io), 70 I/O41 F1 (io), 71 NC, 72 NC, 73 NC, 74 TDO (out), 75 NC, 76 GND (power), 77 NC, 78 NC, 79 I/O42 F2 (io), 80 I/O43 F3 (io), 81 I/O44 F4 (io), 82 I/O45 F5 (io), 83 I/O46 F6 (io), 84 I/O47 F7 (io), 85 NC, 86 I6 (in), 87 NC, 88 NC, 89 GND (power), 90 VCC (power), 91 I7 (in), 92 I/O0 A7 (io), 93 I/O1 A6 (io), 94 I/O2 A5 (io), 95 I/O3 A4 (io), 96 I/O4 A3 (io), 97 I/O5 A2 (io), 98 NC, 99 NC, 100 GND (power)

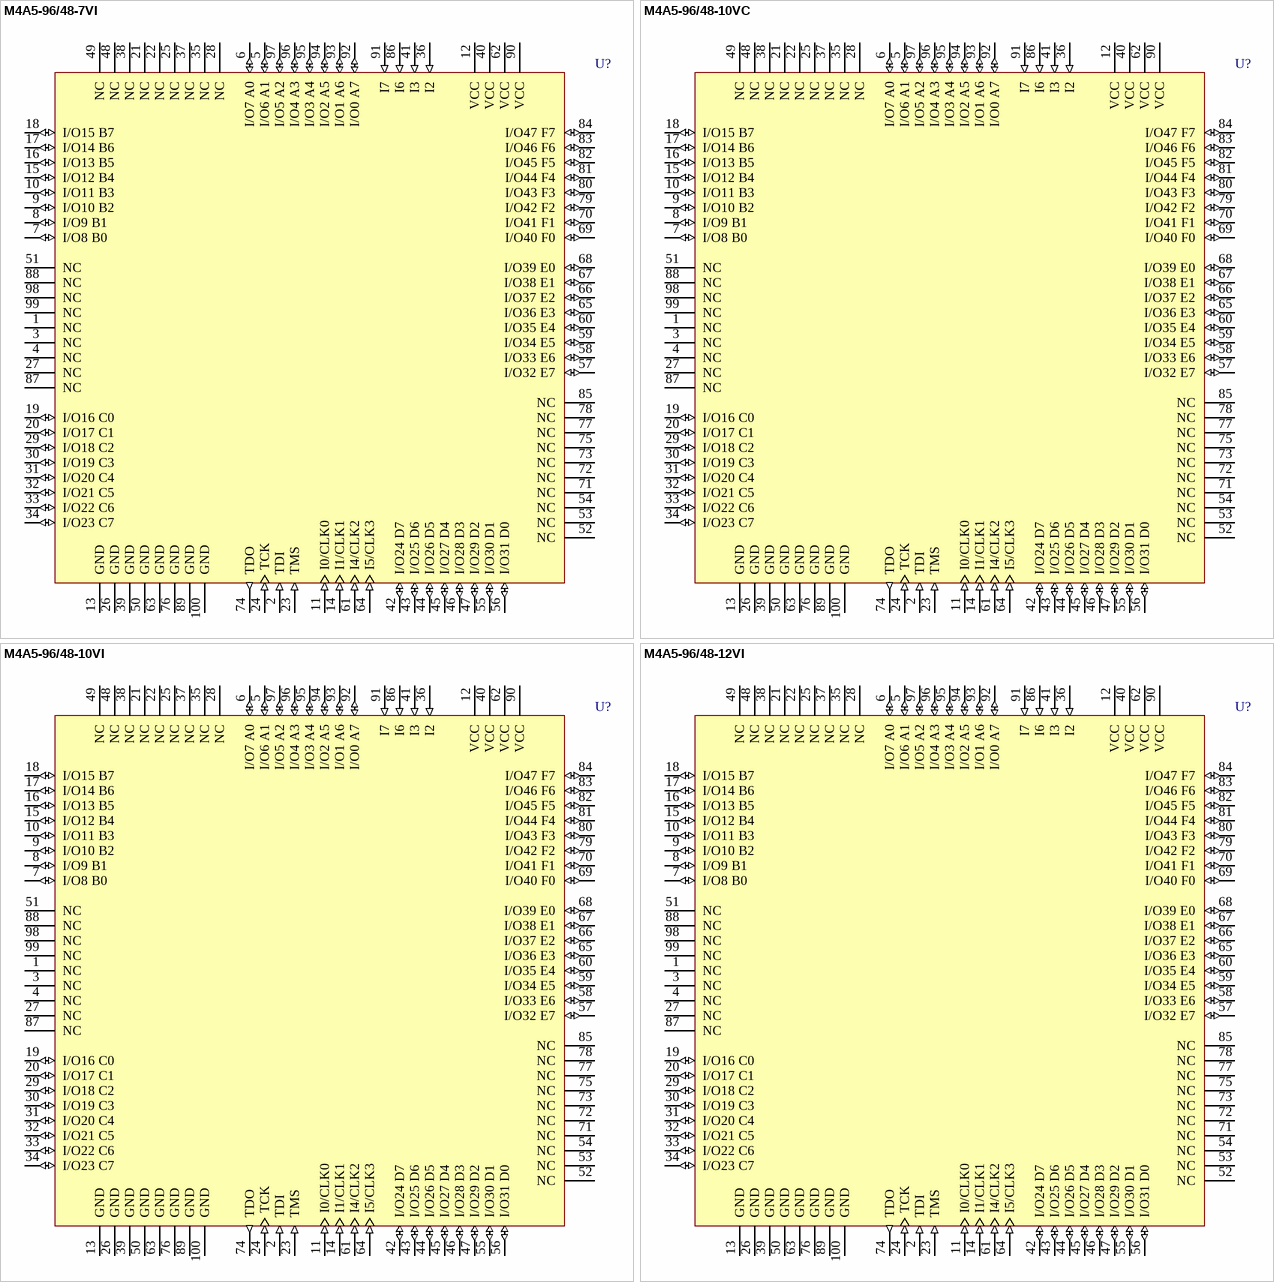
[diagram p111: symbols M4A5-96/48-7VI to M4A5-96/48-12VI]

## M4A5-96/48-7VI
designator U?
High-Performance EE CMOS In-System Programmable Logic
footprint TQFP100_N (Thin QFP, 100-Leads, Body 14x14mm, Pitch 0.5mm, IPC Medium Density)
footprint TQFP100_L (Thin QFP, 100-Leads, Body 14x14mm, Pitch 0.5mm, IPC High Density)
footprint TQFP100_M (Thin QFP, 100-Leads, Body 14x14mm, Pitch 0.5mm, IPC Low Density)
3D model M4A5-TQFP100 (100-Pin Thin Quad Flat Pack (TQFP100))
pins: 1 NC, 2 TDI (in), 3 NC, 4 NC, 5 I/O6 A1 (io), 6 I/O7 A0 (io), 7 I/O8 B0 (io), 8 I/O9 B1 (io), 9 I/O10 B2 (io), 10 I/O11 B3 (io), 11 I0/CLK0 (in), 12 VCC (power), 13 GND (power), 14 I1/CLK1 (in), 15 I/O12 B4 (io), 16 I/O13 B5 (io), 17 I/O14 B6 (io), 18 I/O15 B7 (io), 19 I/O16 C0 (io), 20 I/O17 C1 (io), 21 NC, 22 NC, 23 TMS (in), 24 TCK (in), 25 NC, 26 GND (power), 27 NC, 28 NC, 29 I/O18 C2 (io), 30 I/O19 C3 (io), 31 I/O20 C4 (io), 32 I/O21 C5 (io), 33 I/O22 C6 (io), 34 I/O23 C7 (io), 35 NC, 36 I2 (in), 37 NC, 38 NC, 39 GND (power), 40 VCC (power), 41 I3 (in), 42 I/O24 D7 (io), 43 I/O25 D6 (io), 44 I/O26 D5 (io), 45 I/O27 D4 (io), 46 I/O28 D3 (io), 47 I/O29 D2 (io), 48 NC, 49 NC, 50 GND (power), 51 NC, 52 NC, 53 NC, 54 NC, 55 I/O30 D1 (io), 56 I/O31 D0 (io), 57 I/O32 E7 (io), 58 I/O33 E6 (io), 59 I/O34 E5 (io), 60 I/O35 E4 (io), 61 I4/CLK2 (in), 62 VCC (power), 63 GND (power), 64 I5/CLK3 (in), 65 I/O36 E3 (io), 66 I/O37 E2 (io), 67 I/O38 E1 (io), 68 I/O39 E0 (io), 69 I/O40 F0 (io), 70 I/O41 F1 (io), 71 NC, 72 NC, 73 NC, 74 TDO (out), 75 NC, 76 GND (power), 77 NC, 78 NC, 79 I/O42 F2 (io), 80 I/O43 F3 (io), 81 I/O44 F4 (io), 82 I/O45 F5 (io), 83 I/O46 F6 (io), 84 I/O47 F7 (io), 85 NC, 86 I6 (in), 87 NC, 88 NC, 89 GND (power), 90 VCC (power), 91 I7 (in), 92 I/O0 A7 (io), 93 I/O1 A6 (io), 94 I/O2 A5 (io), 95 I/O3 A4 (io), 96 I/O4 A3 (io), 97 I/O5 A2 (io), 98 NC, 99 NC, 100 GND (power)

## M4A5-96/48-10VC
designator U?
High-Performance EE CMOS In-System Programmable Logic
footprint TQFP100_N (Thin QFP, 100-Leads, Body 14x14mm, Pitch 0.5mm, IPC Medium Density)
footprint TQFP100_L (Thin QFP, 100-Leads, Body 14x14mm, Pitch 0.5mm, IPC High Density)
footprint TQFP100_M (Thin QFP, 100-Leads, Body 14x14mm, Pitch 0.5mm, IPC Low Density)
3D model M4A5-TQFP100 (100-Pin Thin Quad Flat Pack (TQFP100))
pins: 1 NC, 2 TDI (in), 3 NC, 4 NC, 5 I/O6 A1 (io), 6 I/O7 A0 (io), 7 I/O8 B0 (io), 8 I/O9 B1 (io), 9 I/O10 B2 (io), 10 I/O11 B3 (io), 11 I0/CLK0 (in), 12 VCC (power), 13 GND (power), 14 I1/CLK1 (in), 15 I/O12 B4 (io), 16 I/O13 B5 (io), 17 I/O14 B6 (io), 18 I/O15 B7 (io), 19 I/O16 C0 (io), 20 I/O17 C1 (io), 21 NC, 22 NC, 23 TMS (in), 24 TCK (in), 25 NC, 26 GND (power), 27 NC, 28 NC, 29 I/O18 C2 (io), 30 I/O19 C3 (io), 31 I/O20 C4 (io), 32 I/O21 C5 (io), 33 I/O22 C6 (io), 34 I/O23 C7 (io), 35 NC, 36 I2 (in), 37 NC, 38 NC, 39 GND (power), 40 VCC (power), 41 I3 (in), 42 I/O24 D7 (io), 43 I/O25 D6 (io), 44 I/O26 D5 (io), 45 I/O27 D4 (io), 46 I/O28 D3 (io), 47 I/O29 D2 (io), 48 NC, 49 NC, 50 GND (power), 51 NC, 52 NC, 53 NC, 54 NC, 55 I/O30 D1 (io), 56 I/O31 D0 (io), 57 I/O32 E7 (io), 58 I/O33 E6 (io), 59 I/O34 E5 (io), 60 I/O35 E4 (io), 61 I4/CLK2 (in), 62 VCC (power), 63 GND (power), 64 I5/CLK3 (in), 65 I/O36 E3 (io), 66 I/O37 E2 (io), 67 I/O38 E1 (io), 68 I/O39 E0 (io), 69 I/O40 F0 (io), 70 I/O41 F1 (io), 71 NC, 72 NC, 73 NC, 74 TDO (out), 75 NC, 76 GND (power), 77 NC, 78 NC, 79 I/O42 F2 (io), 80 I/O43 F3 (io), 81 I/O44 F4 (io), 82 I/O45 F5 (io), 83 I/O46 F6 (io), 84 I/O47 F7 (io), 85 NC, 86 I6 (in), 87 NC, 88 NC, 89 GND (power), 90 VCC (power), 91 I7 (in), 92 I/O0 A7 (io), 93 I/O1 A6 (io), 94 I/O2 A5 (io), 95 I/O3 A4 (io), 96 I/O4 A3 (io), 97 I/O5 A2 (io), 98 NC, 99 NC, 100 GND (power)

## M4A5-96/48-10VI
designator U?
High-Performance EE CMOS In-System Programmable Logic
footprint TQFP100_N (Thin QFP, 100-Leads, Body 14x14mm, Pitch 0.5mm, IPC Medium Density)
footprint TQFP100_L (Thin QFP, 100-Leads, Body 14x14mm, Pitch 0.5mm, IPC High Density)
footprint TQFP100_M (Thin QFP, 100-Leads, Body 14x14mm, Pitch 0.5mm, IPC Low Density)
3D model M4A5-TQFP100 (100-Pin Thin Quad Flat Pack (TQFP100))
pins: 1 NC, 2 TDI (in), 3 NC, 4 NC, 5 I/O6 A1 (io), 6 I/O7 A0 (io), 7 I/O8 B0 (io), 8 I/O9 B1 (io), 9 I/O10 B2 (io), 10 I/O11 B3 (io), 11 I0/CLK0 (in), 12 VCC (power), 13 GND (power), 14 I1/CLK1 (in), 15 I/O12 B4 (io), 16 I/O13 B5 (io), 17 I/O14 B6 (io), 18 I/O15 B7 (io), 19 I/O16 C0 (io), 20 I/O17 C1 (io), 21 NC, 22 NC, 23 TMS (in), 24 TCK (in), 25 NC, 26 GND (power), 27 NC, 28 NC, 29 I/O18 C2 (io), 30 I/O19 C3 (io), 31 I/O20 C4 (io), 32 I/O21 C5 (io), 33 I/O22 C6 (io), 34 I/O23 C7 (io), 35 NC, 36 I2 (in), 37 NC, 38 NC, 39 GND (power), 40 VCC (power), 41 I3 (in), 42 I/O24 D7 (io), 43 I/O25 D6 (io), 44 I/O26 D5 (io), 45 I/O27 D4 (io), 46 I/O28 D3 (io), 47 I/O29 D2 (io), 48 NC, 49 NC, 50 GND (power), 51 NC, 52 NC, 53 NC, 54 NC, 55 I/O30 D1 (io), 56 I/O31 D0 (io), 57 I/O32 E7 (io), 58 I/O33 E6 (io), 59 I/O34 E5 (io), 60 I/O35 E4 (io), 61 I4/CLK2 (in), 62 VCC (power), 63 GND (power), 64 I5/CLK3 (in), 65 I/O36 E3 (io), 66 I/O37 E2 (io), 67 I/O38 E1 (io), 68 I/O39 E0 (io), 69 I/O40 F0 (io), 70 I/O41 F1 (io), 71 NC, 72 NC, 73 NC, 74 TDO (out), 75 NC, 76 GND (power), 77 NC, 78 NC, 79 I/O42 F2 (io), 80 I/O43 F3 (io), 81 I/O44 F4 (io), 82 I/O45 F5 (io), 83 I/O46 F6 (io), 84 I/O47 F7 (io), 85 NC, 86 I6 (in), 87 NC, 88 NC, 89 GND (power), 90 VCC (power), 91 I7 (in), 92 I/O0 A7 (io), 93 I/O1 A6 (io), 94 I/O2 A5 (io), 95 I/O3 A4 (io), 96 I/O4 A3 (io), 97 I/O5 A2 (io), 98 NC, 99 NC, 100 GND (power)

## M4A5-96/48-12VI
designator U?
High-Performance EE CMOS In-System Programmable Logic
footprint TQFP100_N (Thin QFP, 100-Leads, Body 14x14mm, Pitch 0.5mm, IPC Medium Density)
footprint TQFP100_L (Thin QFP, 100-Leads, Body 14x14mm, Pitch 0.5mm, IPC High Density)
footprint TQFP100_M (Thin QFP, 100-Leads, Body 14x14mm, Pitch 0.5mm, IPC Low Density)
3D model M4A5-TQFP100 (100-Pin Thin Quad Flat Pack (TQFP100))
pins: 1 NC, 2 TDI (in), 3 NC, 4 NC, 5 I/O6 A1 (io), 6 I/O7 A0 (io), 7 I/O8 B0 (io), 8 I/O9 B1 (io), 9 I/O10 B2 (io), 10 I/O11 B3 (io), 11 I0/CLK0 (in), 12 VCC (power), 13 GND (power), 14 I1/CLK1 (in), 15 I/O12 B4 (io), 16 I/O13 B5 (io), 17 I/O14 B6 (io), 18 I/O15 B7 (io), 19 I/O16 C0 (io), 20 I/O17 C1 (io), 21 NC, 22 NC, 23 TMS (in), 24 TCK (in), 25 NC, 26 GND (power), 27 NC, 28 NC, 29 I/O18 C2 (io), 30 I/O19 C3 (io), 31 I/O20 C4 (io), 32 I/O21 C5 (io), 33 I/O22 C6 (io), 34 I/O23 C7 (io), 35 NC, 36 I2 (in), 37 NC, 38 NC, 39 GND (power), 40 VCC (power), 41 I3 (in), 42 I/O24 D7 (io), 43 I/O25 D6 (io), 44 I/O26 D5 (io), 45 I/O27 D4 (io), 46 I/O28 D3 (io), 47 I/O29 D2 (io), 48 NC, 49 NC, 50 GND (power), 51 NC, 52 NC, 53 NC, 54 NC, 55 I/O30 D1 (io), 56 I/O31 D0 (io), 57 I/O32 E7 (io), 58 I/O33 E6 (io), 59 I/O34 E5 (io), 60 I/O35 E4 (io), 61 I4/CLK2 (in), 62 VCC (power), 63 GND (power), 64 I5/CLK3 (in), 65 I/O36 E3 (io), 66 I/O37 E2 (io), 67 I/O38 E1 (io), 68 I/O39 E0 (io), 69 I/O40 F0 (io), 70 I/O41 F1 (io), 71 NC, 72 NC, 73 NC, 74 TDO (out), 75 NC, 76 GND (power), 77 NC, 78 NC, 79 I/O42 F2 (io), 80 I/O43 F3 (io), 81 I/O44 F4 (io), 82 I/O45 F5 (io), 83 I/O46 F6 (io), 84 I/O47 F7 (io), 85 NC, 86 I6 (in), 87 NC, 88 NC, 89 GND (power), 90 VCC (power), 91 I7 (in), 92 I/O0 A7 (io), 93 I/O1 A6 (io), 94 I/O2 A5 (io), 95 I/O3 A4 (io), 96 I/O4 A3 (io), 97 I/O5 A2 (io), 98 NC, 99 NC, 100 GND (power)

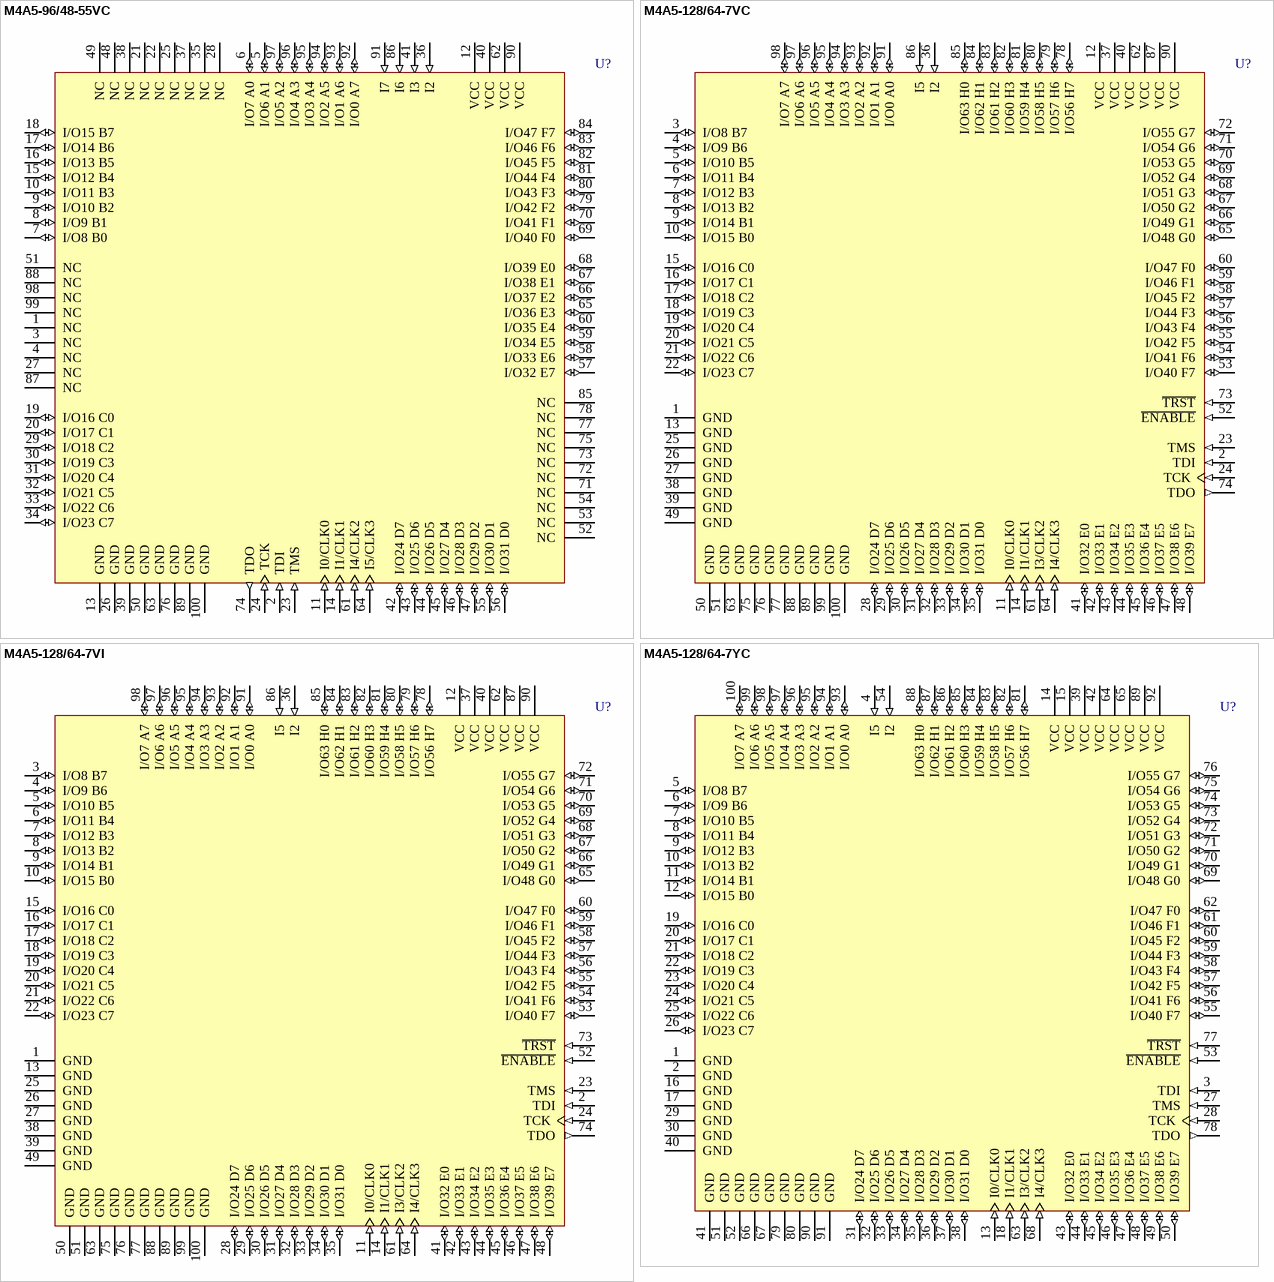
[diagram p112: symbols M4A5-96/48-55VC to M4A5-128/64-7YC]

## M4A5-96/48-55VC
designator U?
High-Performance EE CMOS In-System Programmable Logic
footprint TQFP100_N (Thin QFP, 100-Leads, Body 14x14mm, Pitch 0.5mm, IPC Medium Density)
footprint TQFP100_L (Thin QFP, 100-Leads, Body 14x14mm, Pitch 0.5mm, IPC High Density)
footprint TQFP100_M (Thin QFP, 100-Leads, Body 14x14mm, Pitch 0.5mm, IPC Low Density)
3D model M4A5-TQFP100 (100-Pin Thin Quad Flat Pack (TQFP100))
pins: 1 NC, 2 TDI (in), 3 NC, 4 NC, 5 I/O6 A1 (io), 6 I/O7 A0 (io), 7 I/O8 B0 (io), 8 I/O9 B1 (io), 9 I/O10 B2 (io), 10 I/O11 B3 (io), 11 I0/CLK0 (in), 12 VCC (power), 13 GND (power), 14 I1/CLK1 (in), 15 I/O12 B4 (io), 16 I/O13 B5 (io), 17 I/O14 B6 (io), 18 I/O15 B7 (io), 19 I/O16 C0 (io), 20 I/O17 C1 (io), 21 NC, 22 NC, 23 TMS (in), 24 TCK (in), 25 NC, 26 GND (power), 27 NC, 28 NC, 29 I/O18 C2 (io), 30 I/O19 C3 (io), 31 I/O20 C4 (io), 32 I/O21 C5 (io), 33 I/O22 C6 (io), 34 I/O23 C7 (io), 35 NC, 36 I2 (in), 37 NC, 38 NC, 39 GND (power), 40 VCC (power), 41 I3 (in), 42 I/O24 D7 (io), 43 I/O25 D6 (io), 44 I/O26 D5 (io), 45 I/O27 D4 (io), 46 I/O28 D3 (io), 47 I/O29 D2 (io), 48 NC, 49 NC, 50 GND (power), 51 NC, 52 NC, 53 NC, 54 NC, 55 I/O30 D1 (io), 56 I/O31 D0 (io), 57 I/O32 E7 (io), 58 I/O33 E6 (io), 59 I/O34 E5 (io), 60 I/O35 E4 (io), 61 I4/CLK2 (in), 62 VCC (power), 63 GND (power), 64 I5/CLK3 (in), 65 I/O36 E3 (io), 66 I/O37 E2 (io), 67 I/O38 E1 (io), 68 I/O39 E0 (io), 69 I/O40 F0 (io), 70 I/O41 F1 (io), 71 NC, 72 NC, 73 NC, 74 TDO (out), 75 NC, 76 GND (power), 77 NC, 78 NC, 79 I/O42 F2 (io), 80 I/O43 F3 (io), 81 I/O44 F4 (io), 82 I/O45 F5 (io), 83 I/O46 F6 (io), 84 I/O47 F7 (io), 85 NC, 86 I6 (in), 87 NC, 88 NC, 89 GND (power), 90 VCC (power), 91 I7 (in), 92 I/O0 A7 (io), 93 I/O1 A6 (io), 94 I/O2 A5 (io), 95 I/O3 A4 (io), 96 I/O4 A3 (io), 97 I/O5 A2 (io), 98 NC, 99 NC, 100 GND (power)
